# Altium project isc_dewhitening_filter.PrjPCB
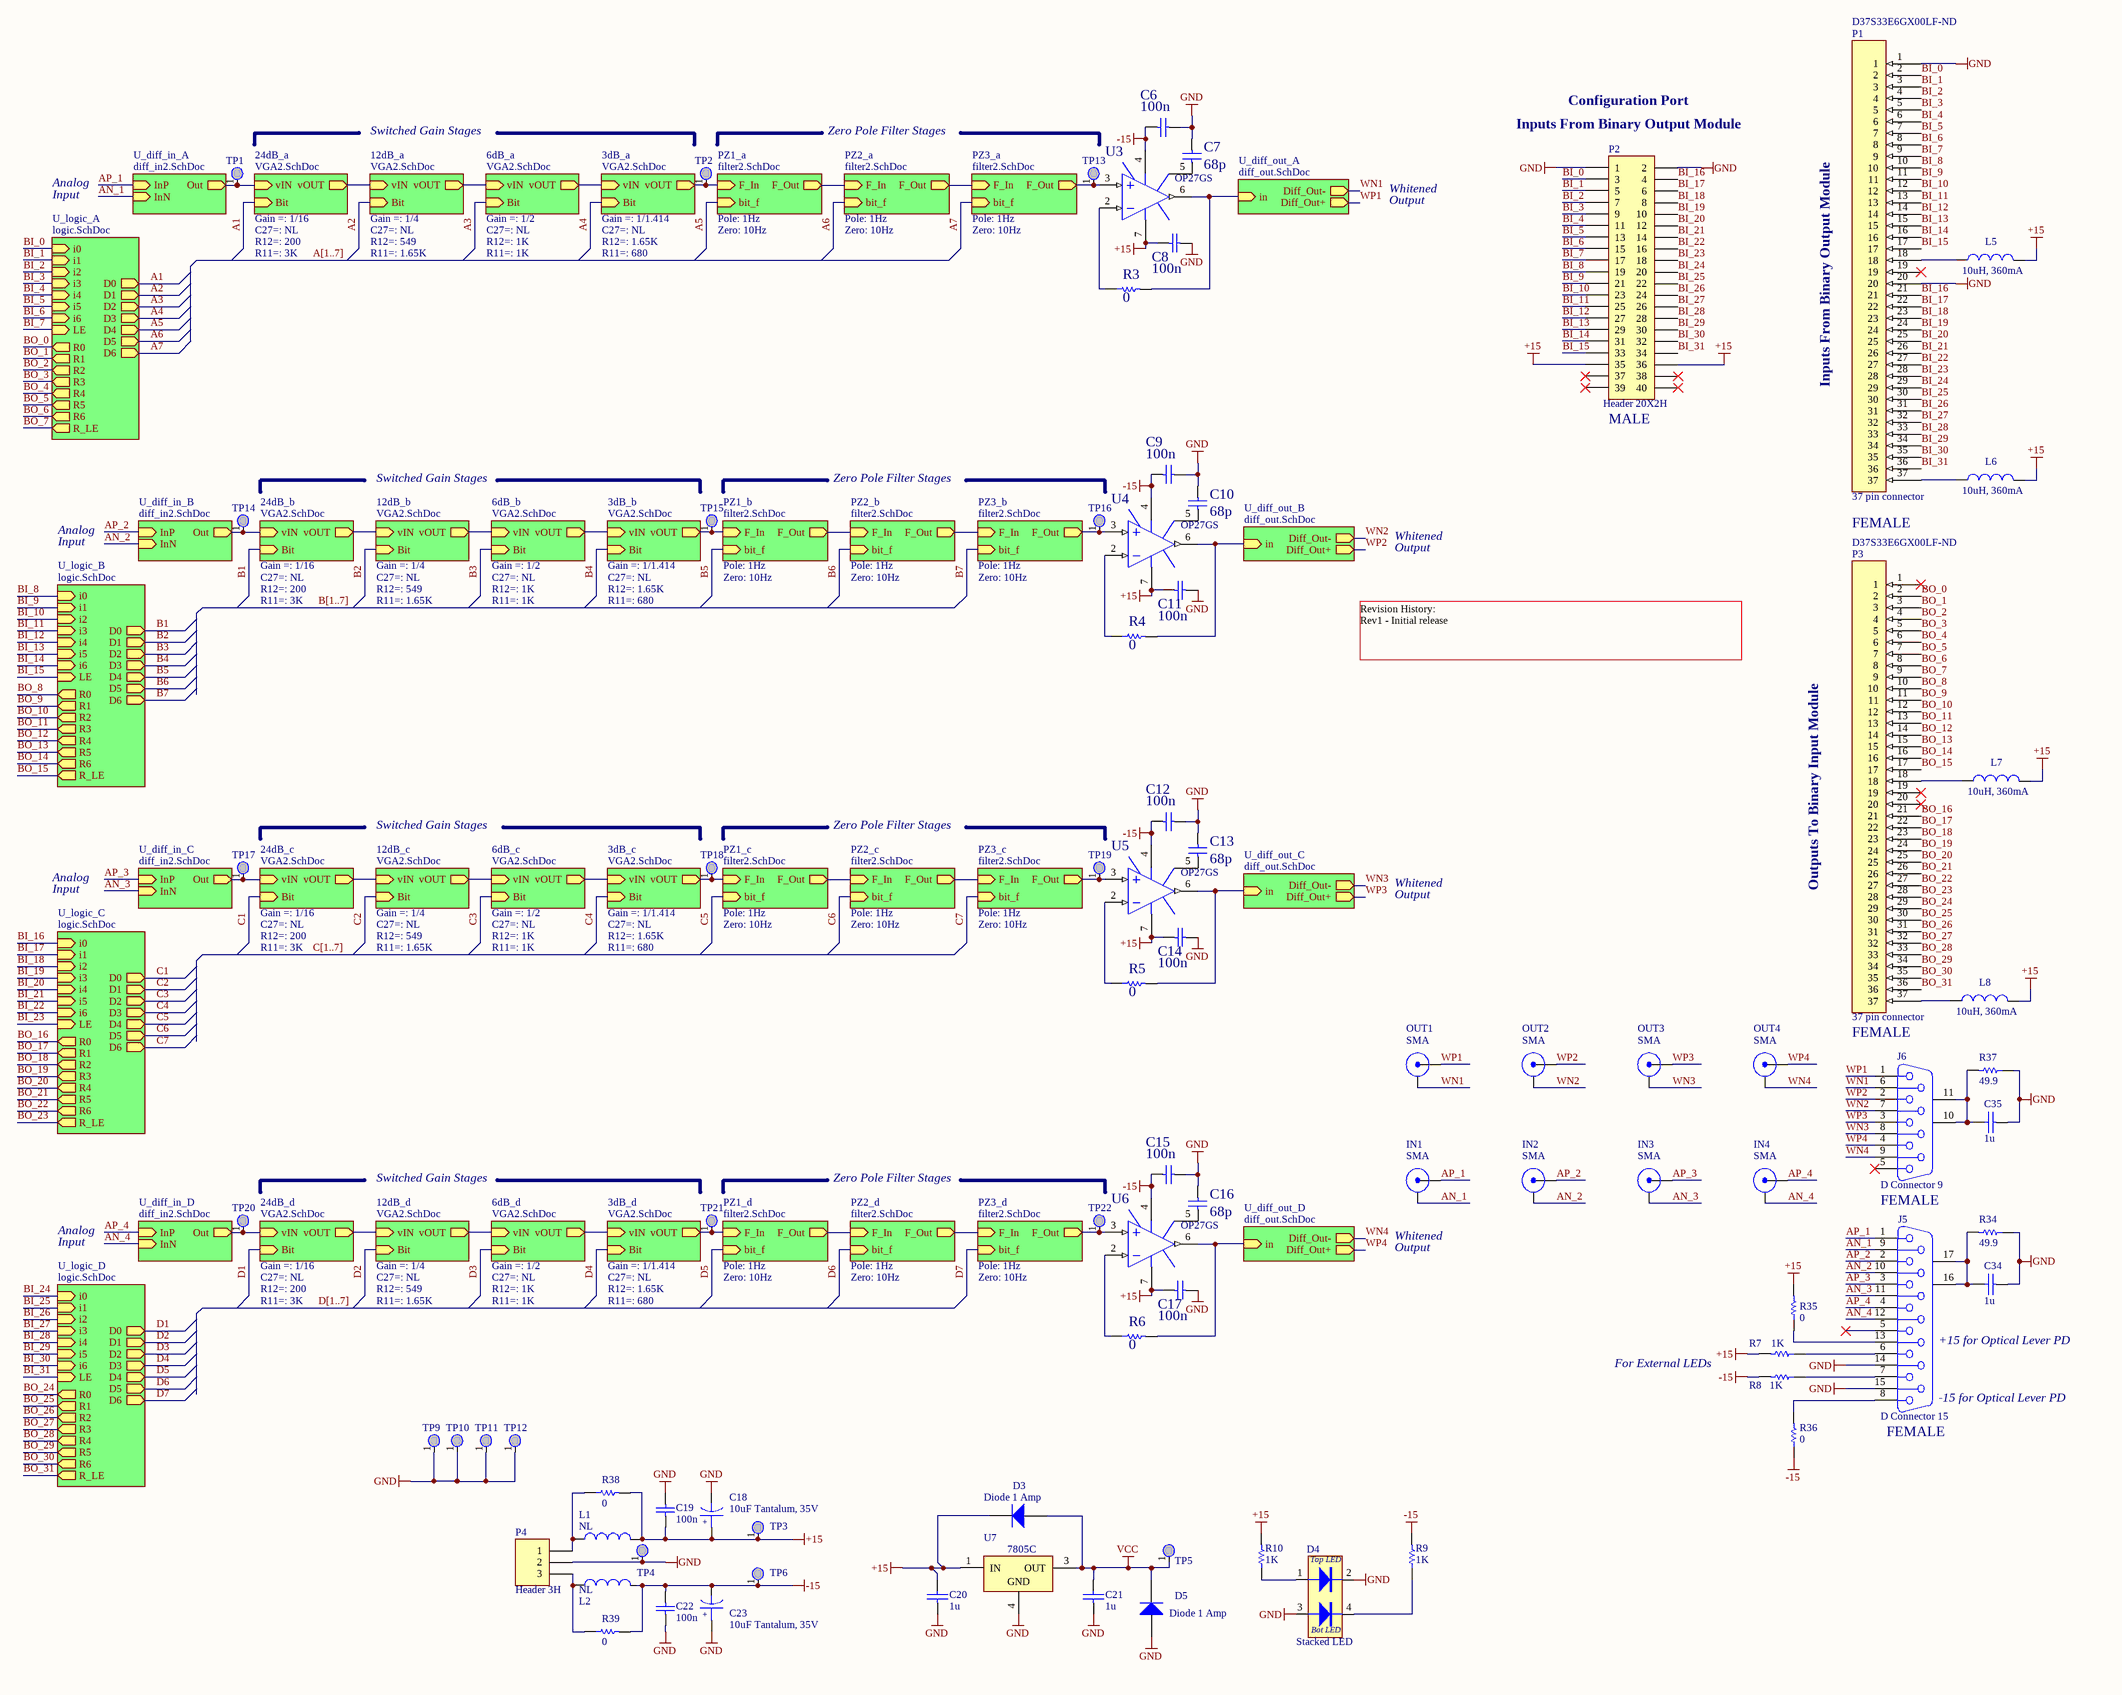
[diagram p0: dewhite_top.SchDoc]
DCC: D2500133; REV: 1
6 sheets, 550 parts. Net scope: hierarchical (ports join the sheet entries above them; power ports are global).
Board file: isc_dewhitening_filter.PcbDoc
Sheets:
  dewhite_top.SchDoc
    24dB_a = VGA2.SchDoc
    12dB_a = VGA2.SchDoc
    6dB_a = VGA2.SchDoc
    3dB_a = VGA2.SchDoc
    U_diff_in_A = diff_in2.SchDoc
    U_diff_out_A = diff_out.SchDoc
    U_logic_A = logic.SchDoc
    U_diff_in_B = diff_in2.SchDoc
    U_diff_out_B = diff_out.SchDoc
    U_logic_B = logic.SchDoc
    U_diff_in_C = diff_in2.SchDoc
    U_diff_out_C = diff_out.SchDoc
    U_logic_C = logic.SchDoc
    U_diff_in_D = diff_in2.SchDoc
    U_diff_out_D = diff_out.SchDoc
    U_logic_D = logic.SchDoc
    24dB_b = VGA2.SchDoc
    12dB_b = VGA2.SchDoc
    12dB_c = VGA2.SchDoc
    12dB_d = VGA2.SchDoc
    24dB_c = VGA2.SchDoc
    24dB_d = VGA2.SchDoc
    6dB_b = VGA2.SchDoc
    6dB_c = VGA2.SchDoc
    6dB_d = VGA2.SchDoc
    3dB_b = VGA2.SchDoc
    3dB_c = VGA2.SchDoc
    3dB_d = VGA2.SchDoc
    PZ1_b = filter2.SchDoc
    PZ2_b = filter2.SchDoc
    PZ3_b = filter2.SchDoc
    PZ1_a = filter2.SchDoc
    PZ2_a = filter2.SchDoc
    PZ3_a = filter2.SchDoc
    PZ1_c = filter2.SchDoc
    PZ2_c = filter2.SchDoc
    PZ3_c = filter2.SchDoc
    PZ1_d = filter2.SchDoc
    PZ2_d = filter2.SchDoc
    PZ3_d = filter2.SchDoc

## Sheet dewhite_top.SchDoc: aLIGO ISC Dewhitening Filter
size C; SchematicNumber: DYYYYYYY-VX; PcbNumber: DXXXXXXX-VX; LastEdit: 06 Oct 2010; PageSetup: Record=PageOptions¦CenterHorizontal=True¦CenterVertical=True¦PrintScale=0.70¦XCorrection=1.00¦YCorrection=1.00¦PrintKind=0¦BorderSize=5000000¦LeftOffset=0¦BottomOffset=0¦Orientation=2¦PaperLength=4318¦PaperWidth=2794¦Scale=100¦PaperSource=7¦PrintQuality=600¦MediaType=1¦DitherType=10¦PaperKind=11x17¦PrintScaleMode=1; Organization: LIGO Laboratory; Address1: California Institute of Technology; Address2: Massachusetts Institute of Technology; DocumentNumber: D2500133; Revision: 1; SheetNumber: 1; SheetTotal: 6; Engineer: R. Abbott/D. Sigg

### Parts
C6  100n  [3216[1206]]
C7  68p  [3216[1206]]
C8  100n  [3216[1206]]
C9  100n  [3216[1206]]
C10  68p  [3216[1206]]
C11  100n  [3216[1206]]
C12  100n  [3216[1206]]
C13  68p  [3216[1206]]
C14  100n  [3216[1206]]
C15  100n  [3216[1206]]
C16  68p  [3216[1206]]
C17  100n  [3216[1206]]
C18  10uF Tantalum, 35V  [7343-31]
C19  100n  [3216[1206]]
C20  1u  [3216[1206]]
C21  1u  [3216[1206]]
C22  100n  [3216[1206]]
C23  10uF Tantalum, 35V  [7343-31]
C34  1u  [3216[1206]]
C35  1u  [3216[1206]]
D3  value Diode 1 Amp  [sod123]  (hidden comment: 60V, 1A Schottky)
D4  Stacked LED  [my LUMEX Dual LED]
D5  value Diode 1 Amp  [sod123]  (hidden comment: 60V, 1A Schottky)
IN1  SMA  [SMA]
IN2  SMA  [SMA]
IN3  SMA  [SMA]
IN4  SMA  [SMA]
J5  D Connector 15  [DSUB1.385-2H15]
J6  D Connector 9  [DSUB1.385-2H9]
L1  NL  [1812]
L2  NL  [1812]
L5  10uH, 360mA  [1812]
L6  10uH, 360mA  [1812]
L7  10uH, 360mA  [1812]
L8  10uH, 360mA  [1812]
OUT1  SMA  [SMA]
OUT2  SMA  [SMA]
OUT3  SMA  [SMA]
OUT4  SMA  [SMA]
P1  37 pin connector  Supplier Part Number 1: D37S33E6GX00LF-ND  [DB37/F/RA/125MT]
P2  Header 20X2H  [MY_40-pin_Header_RA]
P3  37 pin connector  Supplier Part Number 1: D37S33E6GX00LF-ND  [DB37/F/RA/125MT]
P4  Header 3H  [Molex_156_RA_3]
R3  0  [3216[1206]]
R4  0  [3216[1206]]
R5  0  [3216[1206]]
R6  0  [3216[1206]]
R7  1K  [3216[1206]]
R8  1K  [3216[1206]]
R9  1K  [3216[1206]]
R10  1K  [3216[1206]]
R34  49.9  [3216[1206]]
R35  0  [3216[1206]]
R36  0  [3216[1206]]
R37  49.9  [3216[1206]]
R38  0  [3216[1206]]
R39  0  [3216[1206]]
TP1  TEST POINT  [TP_SMT_MICRO]  (value not drawn)
TP2  TEST POINT  [TP_SMT_MICRO]  (value not drawn)
TP3  TEST POINT  [TP_SMT_MICRO]  (value not drawn)
TP4  TEST POINT  [TP_SMT_MICRO]  (value not drawn)
TP5  TEST POINT  [TP_SMT_MICRO]  (value not drawn)
TP6  TEST POINT  [TP_SMT_MICRO]  (value not drawn)
TP9  TEST POINT  [TP_SMT_MICRO]  (value not drawn)
TP10  TEST POINT  [TP_SMT_MICRO]  (value not drawn)
TP11  TEST POINT  [TP_SMT_MICRO]  (value not drawn)
TP12  TEST POINT  [TP_SMT_MICRO]  (value not drawn)
TP13  TEST POINT  [TP_SMT_MICRO]  (value not drawn)
TP14  TEST POINT  [TP_SMT_MICRO]  (value not drawn)
TP15  TEST POINT  [TP_SMT_MICRO]  (value not drawn)
TP16  TEST POINT  [TP_SMT_MICRO]  (value not drawn)
TP17  TEST POINT  [TP_SMT_MICRO]  (value not drawn)
TP18  TEST POINT  [TP_SMT_MICRO]  (value not drawn)
TP19  TEST POINT  [TP_SMT_MICRO]  (value not drawn)
TP20  TEST POINT  [TP_SMT_MICRO]  (value not drawn)
TP21  TEST POINT  [TP_SMT_MICRO]  (value not drawn)
TP22  TEST POINT  [TP_SMT_MICRO]  (value not drawn)
U3  OP27GS  [SOIC127P600-8N]
U4  OP27GS  [SOIC127P600-8N]
U5  OP27GS  [SOIC127P600-8N]
U6  OP27GS  [SOIC127P600-8N]
U7  7805C  [MY_TO220]

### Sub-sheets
3dB_a = VGA2.SchDoc: Bit (in), vIN (in), vOUT (out)  | R12_value: 1.65K; R11_value: 680; C27_value: NL; Gain =: 1/1.414; C27=: NL; R12=: 1.65K; R11=: 680
3dB_b = VGA2.SchDoc: Bit (in), vIN (in), vOUT (out)  | R12_value: 1.65K; R11_value: 680; C27_value: NL; Gain =: 1/1.414; C27=: NL; R12=: 1.65K; R11=: 680
3dB_c = VGA2.SchDoc: Bit (in), vIN (in), vOUT (out)  | R12_value: 1.65K; R11_value: 680; C27_value: NL; Gain =: 1/1.414; C27=: NL; R12=: 1.65K; R11=: 680
3dB_d = VGA2.SchDoc: Bit (in), vIN (in), vOUT (out)  | R12_value: 1.65K; R11_value: 680; C27_value: NL; Gain =: 1/1.414; C27=: NL; R12=: 1.65K; R11=: 680
6dB_a = VGA2.SchDoc: Bit (in), vIN (in), vOUT (out)  | C27_value: NL; Gain =: 1/2; R12_Value: 1K; R11_value: 1K; R12=: 1K; R11=: 1K; C27=: NL
6dB_b = VGA2.SchDoc: Bit (in), vIN (in), vOUT (out)  | C27_value: NL; Gain =: 1/2; R12_Value: 1K; R11_value: 1K; R12=: 1K; R11=: 1K; C27=: NL
6dB_c = VGA2.SchDoc: Bit (in), vIN (in), vOUT (out)  | C27_value: NL; Gain =: 1/2; R12_Value: 1K; R11_value: 1K; R12=: 1K; R11=: 1K; C27=: NL
6dB_d = VGA2.SchDoc: Bit (in), vIN (in), vOUT (out)  | C27_value: NL; Gain =: 1/2; R12_Value: 1K; R11_value: 1K; R12=: 1K; R11=: 1K; C27=: NL
12dB_a = VGA2.SchDoc: Bit (in), vIN (in), vOUT (out)  | C27_value: NL; Gain =: 1/4; R12=: 549; R12_value: 549; R11=: 1.65K; R11_value: 1.65K; C27=: NL
12dB_b = VGA2.SchDoc: Bit (in), vIN (in), vOUT (out)  | C27_value: NL; Gain =: 1/4; R12=: 549; R12_value: 549; R11=: 1.65K; R11_value: 1.65K; C27=: NL
12dB_c = VGA2.SchDoc: Bit (in), vIN (in), vOUT (out)  | C27_value: NL; Gain =: 1/4; R12=: 549; R12_value: 549; R11=: 1.65K; R11_value: 1.65K; C27=: NL
12dB_d = VGA2.SchDoc: Bit (in), vIN (in), vOUT (out)  | C27_value: NL; Gain =: 1/4; R12=: 549; R12_value: 549; R11=: 1.65K; R11_value: 1.65K; C27=: NL
24dB_a = VGA2.SchDoc: Bit (in), vIN (in), vOUT (out)  | C27=: NL; C27_value: NL; R12=: 200; R11=: 3K; R11_value: 3K; R12_value: 200; Gain =: 1/16
24dB_b = VGA2.SchDoc: Bit (in), vIN (in), vOUT (out)  | C27=: NL; C27_value: NL; R12=: 200; R11=: 3K; R11_value: 3K; R12_value: 200; Gain =: 1/16
24dB_c = VGA2.SchDoc: Bit (in), vIN (in), vOUT (out)  | C27=: NL; C27_value: NL; R12=: 200; R11=: 3K; R11_value: 3K; R12_value: 200; Gain =: 1/16
24dB_d = VGA2.SchDoc: Bit (in), vIN (in), vOUT (out)  | C27=: NL; C27_value: NL; R12=: 200; R11=: 3K; R11_value: 3K; R12_value: 200; Gain =: 1/16
PZ1_a = filter2.SchDoc: bit_f (in), F_Out (out), F_In (in)  | Pole: 1Hz; Zero: 10Hz; C5_value: 10e-6
PZ1_b = filter2.SchDoc: bit_f (in), F_Out (out), F_In (in)  | Pole: 1Hz; Zero: 10Hz; C5_value: 10e-6
PZ1_c = filter2.SchDoc: bit_f (in), F_Out (out), F_In (in)  | Pole: 1Hz; Zero: 10Hz; C5_value: 10e-6
PZ1_d = filter2.SchDoc: bit_f (in), F_Out (out), F_In (in)  | Pole: 1Hz; Zero: 10Hz; C5_value: 10e-6
PZ2_a = filter2.SchDoc: bit_f (in), F_Out (out), F_In (in)  | Pole: 1Hz; Zero: 10Hz; C5_value: 10e-6
PZ2_b = filter2.SchDoc: bit_f (in), F_Out (out), F_In (in)  | Pole: 1Hz; Zero: 10Hz; C5_value: 10e-6
PZ2_c = filter2.SchDoc: bit_f (in), F_Out (out), F_In (in)  | Pole: 1Hz; Zero: 10Hz; C5_value: 10e-6
PZ2_d = filter2.SchDoc: bit_f (in), F_Out (out), F_In (in)  | Pole: 1Hz; Zero: 10Hz; C5_value: 10e-6
PZ3_a = filter2.SchDoc: bit_f (in), F_Out (out), F_In (in)  | Pole: 1Hz; Zero: 10Hz; C5_value: 10e-6
PZ3_b = filter2.SchDoc: bit_f (in), F_Out (out), F_In (in)  | Pole: 1Hz; Zero: 10Hz; C5_value: 10e-6
PZ3_c = filter2.SchDoc: bit_f (in), F_Out (out), F_In (in)  | Pole: 1Hz; Zero: 10Hz; C5_value: 10e-6
PZ3_d = filter2.SchDoc: bit_f (in), F_Out (out), F_In (in)  | Pole: 1Hz; Zero: 10Hz; C5_value: 10e-6
U_diff_in_A = diff_in2.SchDoc: InP (in), InN (in), Out (out)
U_diff_in_B = diff_in2.SchDoc: InP (in), InN (in), Out (out)
U_diff_in_C = diff_in2.SchDoc: InP (in), InN (in), Out (out)
U_diff_in_D = diff_in2.SchDoc: InP (in), InN (in), Out (out)
U_diff_out_A = diff_out.SchDoc: Diff_Out- (out), Diff_Out+ (out), in (in)
U_diff_out_B = diff_out.SchDoc: Diff_Out- (out), Diff_Out+ (out), in (in)
U_diff_out_C = diff_out.SchDoc: Diff_Out- (out), Diff_Out+ (out), in (in)
U_diff_out_D = diff_out.SchDoc: Diff_Out- (out), Diff_Out+ (out), in (in)
U_logic_A = logic.SchDoc: D0 (out), D1 (out), D2 (out), D3 (out), D4 (out), D5 (out), D6 (out), R0 (out), R1 (out), R2 (out), R3 (out), R4 (out), R5 (out), R6 (out), R_LE (out), i0 (in), i1 (in), i2 (in), i3 (in), i4 (in), i5 (in), i6 (in), LE (in)
U_logic_B = logic.SchDoc: D0 (out), D1 (out), D2 (out), D3 (out), D4 (out), D5 (out), D6 (out), R0 (out), R1 (out), R2 (out), R3 (out), R4 (out), R5 (out), R6 (out), R_LE (out), i0 (in), i1 (in), i2 (in), i3 (in), i4 (in), i5 (in), i6 (in), LE (in)
U_logic_C = logic.SchDoc: D0 (out), D1 (out), D2 (out), D3 (out), D4 (out), D5 (out), D6 (out), R0 (out), R1 (out), R2 (out), R3 (out), R4 (out), R5 (out), R6 (out), R_LE (out), i0 (in), i1 (in), i2 (in), i3 (in), i4 (in), i5 (in), i6 (in), LE (in)
U_logic_D = logic.SchDoc: D0 (out), D1 (out), D2 (out), D3 (out), D4 (out), D5 (out), D6 (out), R0 (out), R1 (out), R2 (out), R3 (out), R4 (out), R5 (out), R6 (out), R_LE (out), i0 (in), i1 (in), i2 (in), i3 (in), i4 (in), i5 (in), i6 (in), LE (in)

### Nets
+15: C8.2 C11.2 C14.2 C17.2 C18.1 C19.1 C20.2 D3.2(K) L1.2 L5.2 L6.2 L7.2 L8.2 P2.35 P2.36 R7.2 R10.2 R35.2 R38.2 TP3.1 U3.7(V+) U4.7(V+) U5.7(V+) U6.7(V+) U7.1(IN)
-15: C6.2 C9.2 C12.2 C15.2 C22.1 C23.2 L2.2 R8.2 R9.2 R36.1 R39.2 TP6.1 U3.4(V-) U4.4(V-) U5.4(V-) U6.4(V-)
GND: C6.1 C7.1 C8.1 C9.1 C10.1 C11.1 C12.1 C13.1 C14.1 C15.1 C16.1 C17.1 C18.2 C19.2 C20.1 C21.1 C22.2 C23.1 C34.1 C35.1 D4.2(CATHODE) D4.3(ANODE) D5.1(A) J5.14 J5.15 P1.1 P1.20 P2.1 P2.2 P4.2 R34.1 R37.1 TP4.1 TP9.1 TP10.1 TP11.1 TP12.1 U7.4(GND)
VCC: C21.2 D3.1(A) D5.2(K) TP5.1 U7.3(OUT)
A1: sheet 24dB_a/Bit, sheet U_logic_A/D0
A2: sheet 12dB_a/Bit, sheet U_logic_A/D1
A3: sheet 6dB_a/Bit, sheet U_logic_A/D2
A4: sheet 3dB_a/Bit, sheet U_logic_A/D3
A5: sheet U_logic_A/D4, sheet PZ1_a/bit_f
A6: sheet U_logic_A/D5, sheet PZ2_a/bit_f
A7: sheet U_logic_A/D6, sheet PZ3_a/bit_f
AN_1: IN1.2(Y) J5.9 ; sheet U_diff_in_A/InN
AN_2: IN2.2(Y) J5.10 ; sheet U_diff_in_B/InN
AN_3: IN3.2(Y) J5.11 ; sheet U_diff_in_C/InN
AN_4: IN4.2(Y) J5.12 ; sheet U_diff_in_D/InN
AP_1: IN1.1(X) J5.1 ; sheet U_diff_in_A/InP
AP_2: IN2.1(X) J5.2 ; sheet U_diff_in_B/InP
AP_3: IN3.1(X) J5.3 ; sheet U_diff_in_C/InP
AP_4: IN4.1(X) J5.4 ; sheet U_diff_in_D/InP
B1: sheet U_logic_B/D0, sheet 24dB_b/Bit
B2: sheet U_logic_B/D1, sheet 12dB_b/Bit
B3: sheet U_logic_B/D2, sheet 6dB_b/Bit
B4: sheet U_logic_B/D3, sheet 3dB_b/Bit
B5: sheet U_logic_B/D4, sheet PZ1_b/bit_f
B6: sheet U_logic_B/D5, sheet PZ2_b/bit_f
B7: sheet U_logic_B/D6, sheet PZ3_b/bit_f
BI_0: P1.2 P2.3 ; sheet U_logic_A/i0
BI_1: P1.3 P2.5 ; sheet U_logic_A/i1
BI_2: P1.4 P2.7 ; sheet U_logic_A/i2
BI_3: P1.5 P2.9 ; sheet U_logic_A/i3
BI_4: P1.6 P2.11 ; sheet U_logic_A/i4
BI_5: P1.7 P2.13 ; sheet U_logic_A/i5
BI_6: P1.8 P2.15 ; sheet U_logic_A/i6
BI_7: P1.9 P2.17 ; sheet U_logic_A/LE
BI_8: P1.10 P2.19 ; sheet U_logic_B/i0
BI_9: P1.11 P2.21 ; sheet U_logic_B/i1
BI_10: P1.12 P2.23 ; sheet U_logic_B/i2
BI_11: P1.13 P2.25 ; sheet U_logic_B/i3
BI_12: P1.14 P2.27 ; sheet U_logic_B/i4
BI_13: P1.15 P2.29 ; sheet U_logic_B/i5
BI_14: P1.16 P2.31 ; sheet U_logic_B/i6
BI_15: P1.17 P2.33 ; sheet U_logic_B/LE
BI_16: P1.21 P2.4 ; sheet U_logic_C/i0
BI_17: P1.22 P2.6 ; sheet U_logic_C/i1
BI_18: P1.23 P2.8 ; sheet U_logic_C/i2
BI_19: P1.24 P2.10 ; sheet U_logic_C/i3
BI_20: P1.25 P2.12 ; sheet U_logic_C/i4
BI_21: P1.26 P2.14 ; sheet U_logic_C/i5
BI_22: P1.27 P2.16 ; sheet U_logic_C/i6
BI_23: P1.28 P2.18 ; sheet U_logic_C/LE
BI_24: P1.29 P2.20 ; sheet U_logic_D/i0
BI_25: P1.30 P2.22 ; sheet U_logic_D/i1
BI_26: P1.31 P2.24 ; sheet U_logic_D/i2
BI_27: P1.32 P2.26 ; sheet U_logic_D/i3
BI_28: P1.33 P2.28 ; sheet U_logic_D/i4
BI_29: P1.34 P2.30 ; sheet U_logic_D/i5
BI_30: P1.35 P2.32 ; sheet U_logic_D/i6
BI_31: P1.36 P2.34 ; sheet U_logic_D/LE
BO_0: P3.2 ; sheet U_logic_A/R0
BO_1: P3.3 ; sheet U_logic_A/R1
BO_2: P3.4 ; sheet U_logic_A/R2
BO_3: P3.5 ; sheet U_logic_A/R3
BO_4: P3.6 ; sheet U_logic_A/R4
BO_5: P3.7 ; sheet U_logic_A/R5
BO_6: P3.8 ; sheet U_logic_A/R6
BO_7: P3.9 ; sheet U_logic_A/R_LE
BO_8: P3.10 ; sheet U_logic_B/R0
BO_9: P3.11 ; sheet U_logic_B/R1
BO_10: P3.12 ; sheet U_logic_B/R2
BO_11: P3.13 ; sheet U_logic_B/R3
BO_12: P3.14 ; sheet U_logic_B/R4
BO_13: P3.15 ; sheet U_logic_B/R5
BO_14: P3.16 ; sheet U_logic_B/R6
BO_15: P3.17 ; sheet U_logic_B/R_LE
BO_16: P3.21 ; sheet U_logic_C/R0
BO_17: P3.22 ; sheet U_logic_C/R1
BO_18: P3.23 ; sheet U_logic_C/R2
BO_19: P3.24 ; sheet U_logic_C/R3
BO_20: P3.25 ; sheet U_logic_C/R4
BO_21: P3.26 ; sheet U_logic_C/R5
BO_22: P3.27 ; sheet U_logic_C/R6
BO_23: P3.28 ; sheet U_logic_C/R_LE
BO_24: P3.29 ; sheet U_logic_D/R0
BO_25: P3.30 ; sheet U_logic_D/R1
BO_26: P3.31 ; sheet U_logic_D/R2
BO_27: P3.32 ; sheet U_logic_D/R3
BO_28: P3.33 ; sheet U_logic_D/R4
BO_29: P3.34 ; sheet U_logic_D/R5
BO_30: P3.35 ; sheet U_logic_D/R6
BO_31: P3.36 ; sheet U_logic_D/R_LE
C1: sheet U_logic_C/D0, sheet 24dB_c/Bit
C2: sheet U_logic_C/D1, sheet 12dB_c/Bit
C3: sheet U_logic_C/D2, sheet 6dB_c/Bit
C4: sheet U_logic_C/D3, sheet 3dB_c/Bit
C5: sheet U_logic_C/D4, sheet PZ1_c/bit_f
C6: sheet U_logic_C/D5, sheet PZ2_c/bit_f
C7: sheet U_logic_C/D6, sheet PZ3_c/bit_f
D1: sheet U_logic_D/D0, sheet 24dB_d/Bit
D2: sheet U_logic_D/D1, sheet 12dB_d/Bit
D3: sheet U_logic_D/D2, sheet 6dB_d/Bit
D4: sheet U_logic_D/D3, sheet 3dB_d/Bit
D5: sheet U_logic_D/D4, sheet PZ1_d/bit_f
D6: sheet U_logic_D/D5, sheet PZ2_d/bit_f
D7: sheet U_logic_D/D6, sheet PZ3_d/bit_f
WN1: J6.6 OUT1.2(Y) ; sheet U_diff_out_A/Diff_Out-
WN2: J6.7 OUT2.2(Y) ; sheet U_diff_out_B/Diff_Out-
WN3: J6.8 OUT3.2(Y) ; sheet U_diff_out_C/Diff_Out-
WN4: J6.9 OUT4.2(Y) ; sheet U_diff_out_D/Diff_Out-
WP1: J6.1 OUT1.1(X) ; sheet U_diff_out_A/Diff_Out+
WP2: J6.2 OUT2.1(X) ; sheet U_diff_out_B/Diff_Out+
WP3: J6.3 OUT3.1(X) ; sheet U_diff_out_C/Diff_Out+
WP4: J6.4 OUT4.1(X) ; sheet U_diff_out_D/Diff_Out+
NetC7_2: C7.2 U3.5(NUL)
NetC10_2: C10.2 U4.5(NUL)
NetC13_2: C13.2 U5.5(NUL)
NetC16_2: C16.2 U6.5(NUL)
NetC34_2: C34.2 J5.16(MH1) J5.17(MH2) R34.2
NetC35_2: C35.2 J6.10(MH1) J6.11(MH2) R37.2
NetC39_U_diff_in_A_2: TP1.1 ; sheet 24dB_a/vIN, sheet U_diff_in_A/Out
NetC39_U_diff_in_B_2: TP14.1 ; sheet U_diff_in_B/Out, sheet 24dB_b/vIN
NetC39_U_diff_in_C_2: TP17.1 ; sheet U_diff_in_C/Out, sheet 24dB_c/vIN
NetC39_U_diff_in_D_2: TP20.1 ; sheet U_diff_in_D/Out, sheet 24dB_d/vIN
NetD4_1: D4.1(COM) R10.1
NetD4_4: D4.4(ANODE) R9.1
NetJ5_6: J5.6 R7.1
NetJ5_7: J5.7 R8.1
NetJ5_8: J5.8 R36.2
NetJ5_13: J5.13 R35.1
NetL1_1: L1.1 P4.1 R38.1
NetL2_1: L2.1 P4.3 R39.1
NetL5_1: L5.1 P1.18
NetL6_1: L6.1 P1.37
NetL7_1: L7.1 P3.18
NetL8_1: L8.1 P3.37
NetR3_1: R3.1 U3.2(IN-)
NetR3_2: R3.2 U3.6(OUT) ; sheet U_diff_out_A/in
NetR4_1: R4.1 U4.2(IN-)
NetR4_2: R4.2 U4.6(OUT) ; sheet U_diff_out_B/in
NetR5_1: R5.1 U5.2(IN-)
NetR5_2: R5.2 U5.6(OUT) ; sheet U_diff_out_C/in
NetR6_1: R6.1 U6.2(IN-)
NetR6_2: R6.2 U6.6(OUT) ; sheet U_diff_out_D/in
NetTP2_1: TP2.1 ; sheet 3dB_a/vOUT, sheet PZ1_a/F_In
NetTP13_1: TP13.1 U3.3(IN+) ; sheet PZ3_a/F_Out
NetTP15_1: TP15.1 ; sheet 3dB_b/vOUT, sheet PZ1_b/F_In
NetTP16_1: TP16.1 U4.3(IN+) ; sheet PZ3_b/F_Out
NetTP18_1: TP18.1 ; sheet 3dB_c/vOUT, sheet PZ1_c/F_In
NetTP19_1: TP19.1 U5.3(IN+) ; sheet PZ3_c/F_Out
NetTP21_1: TP21.1 ; sheet 3dB_d/vOUT, sheet PZ1_d/F_In
NetTP22_1: TP22.1 U6.3(IN+) ; sheet PZ3_d/F_Out
NetU2_PZ1_a_11: sheet PZ1_a/F_Out, sheet PZ2_a/F_In
NetU2_PZ1_b_11: sheet PZ1_b/F_Out, sheet PZ2_b/F_In
NetU2_PZ1_c_11: sheet PZ1_c/F_Out, sheet PZ2_c/F_In
NetU2_PZ1_d_11: sheet PZ1_d/F_Out, sheet PZ2_d/F_In
NetU2_PZ2_a_11: sheet PZ2_a/F_Out, sheet PZ3_a/F_In
NetU2_PZ2_b_11: sheet PZ2_b/F_Out, sheet PZ3_b/F_In
NetU2_PZ2_c_11: sheet PZ2_c/F_Out, sheet PZ3_c/F_In
NetU2_PZ2_d_11: sheet PZ2_d/F_Out, sheet PZ3_d/F_In
NetU8_3dB_a_4: sheet 6dB_a/vOUT, sheet 3dB_a/vIN
NetU8_3dB_b_4: sheet 6dB_b/vOUT, sheet 3dB_b/vIN
NetU8_3dB_c_4: sheet 6dB_c/vOUT, sheet 3dB_c/vIN
NetU8_3dB_d_4: sheet 6dB_d/vOUT, sheet 3dB_d/vIN
NetU8_6dB_a_4: sheet 12dB_a/vOUT, sheet 6dB_a/vIN
NetU8_6dB_b_4: sheet 12dB_b/vOUT, sheet 6dB_b/vIN
NetU8_6dB_c_4: sheet 12dB_c/vOUT, sheet 6dB_c/vIN
NetU8_6dB_d_4: sheet 12dB_d/vOUT, sheet 6dB_d/vIN
NetU8_12dB_a_4: sheet 24dB_a/vOUT, sheet 12dB_a/vIN
NetU8_12dB_b_4: sheet 24dB_b/vOUT, sheet 12dB_b/vIN
NetU8_12dB_c_4: sheet 12dB_c/vIN, sheet 24dB_c/vOUT
NetU8_12dB_d_4: sheet 12dB_d/vIN, sheet 24dB_d/vOUT

Not connected (* = marked no-connect by the designer): J5 5*; J6 5*; P1 19*; P2 37* 38* 39* 40*; P3 1* 19* 20*; U3 1(NUL) 8(NC); U4 1(NUL) 8(NC); U5 1(NUL) 8(NC); U6 1(NUL) 8(NC)

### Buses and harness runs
bus A[1..7]
bus B[1..7]
bus C[1..7]
bus D[1..7]

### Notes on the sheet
- Configuration Port
- Switched Gain Stages
- Zero Pole Filter Stages
- (near P2) Inputs From Binary Output Module
- Analog
- Input
- Whitened
- Output
- Inputs From Binary Output Module
- (near P2) MALE
- FEMALE
- Revision History:
  Rev1 - Initial release
- Outputs To Binary Input Module
- (near IN1) Whitened
- For External LEDs
- (near J5) +15 for Optical Lever PD
- (near J5) -15 for Optical Lever PD
- (near J5) FEMALE

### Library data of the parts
C6-C17 C19 C22 = Cap: Capacitor
C18 C23 = CAPACITOR POL: Polarized Cap
C20 C21 C34 C35 = MYCAP: Capacitor
D3 D5 = Diode: Diode 1 Amp
D4 = Dual Stacked LED: Dual Green LED
IN1-IN4 OUT1-OUT4 = SMA: SMA, PCB Mount, Right Angle
J5 = D Connector 15: 15 Position, Right Angle, Receptacle Assembly; Value: 15 pin connector Receptacle
J6 = D Connector 9: 9 Position, Right Angle,Receptacle Assembly; Value: 9 pin connector Receptacle
L1 L2 L5-L8 = INDUCTOR
P1 P3 = 37 pin connector: Standard D-Subminiature Connector 37 pin; Value: 37 pin connector Receptacle
P2 = Header 20X2H: Header, 20-Pin, Dual row, Right Angle
P4 = Header 3H: Header, 3-Pin, Right Angle
R3-R10 R34-R39 = Res1: Resistor
TP1-TP6 TP9-TP22 = TESTPT: PCB Testpoint
U3-U6 = OP184ES: Video Operational Amplifier
U7 = MC7805CD2T: Three-Terminal Positive Voltage Regulator

## Sheet VGA2.SchDoc: Variable Gain Stage (Dewhitening)
size A; SchematicNumber: DYYYYYYY-VX; PcbNumber: DXXXXXXX-VX; LastEdit: 06 Oct 2010; Organization: LIGO Laboratory; Address1: California Institute of Technology; Address2: Massachusetts Institute of Technology; DocumentNumber: D2500133; Revision: 1; SheetNumber: 5; SheetTotal: 9; Engineer: R. Abbott/D. Sigg; PageSetup: Record=PageOptions¦CenterHorizontal=True¦CenterVertical=True¦PrintScale=1.40¦XCorrection=1.00¦YCorrection=1.00¦PrintKind=0¦BorderSize=5000000¦LeftOffset=0¦BottomOffset=0¦Orientation=2¦PaperLength=4318¦PaperWidth=2794¦Scale=100¦PaperSource=15¦PrintQuality=600¦MediaType=1¦DitherType=10¦PaperKind=11x17¦PrintScaleMode=1
Used 16 times, as channels 24dB_a, 12dB_a, 6dB_a, 3dB_a, 24dB_b, 12dB_b, 12dB_c, 12dB_d, 24dB_c, 24dB_d, 6dB_b, 6dB_c, 6dB_d, 3dB_b, 3dB_c, 3dB_d. Parts and nets are listed once, with the designators drawn on the sheet.
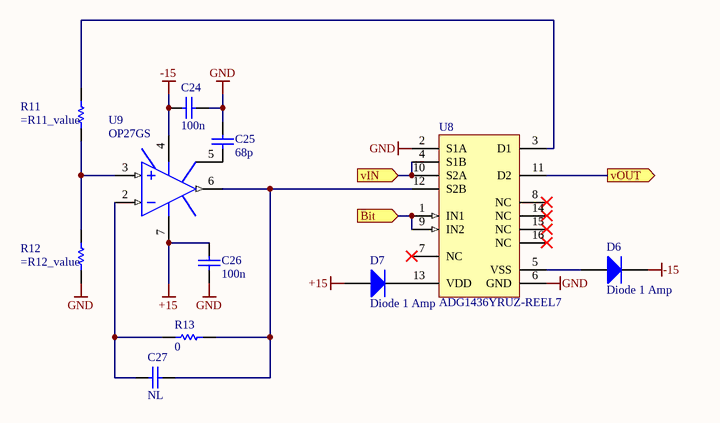
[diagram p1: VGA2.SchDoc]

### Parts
C24  100n  [3216[1206]]
C25  68p  [3216[1206]]
C26  100n  [3216[1206]]
C27  NL  [3216[1206]]
D6  value Diode 1 Amp  [sod123]  (hidden comment: 60V, 1A Schottky)
D7  value Diode 1 Amp  [sod123]  (hidden comment: 60V, 1A Schottky)
R11  (no value)  [3216[1206]]
R12  (no value)  [3216[1206]]
R13  0  [3216[1206]]
U8  ADG1436YRUZ-REEL7  [ADI-RU-16_L]
U9  OP27GS  [SOIC127P600-8N]

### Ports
Bit (in), vIN (in), vOUT (out)

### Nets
+15: C26.2 D7.1(A) U9.7(V+)
-15: C24.2 D6.2(K) U9.4(V-)
GND: C24.1 C25.1 C26.1 R12.1 U8.2(S1A) U8.6(GND)
Bit: U8.1(IN1) U8.9(IN2) ; port Bit
vIN: U8.4(S1B) U8.10(S2A) ; port vIN
vOUT: U8.11(D2) ; port vOUT
NetC25_2: C25.2 U9.5(NUL)
NetC27_1: C27.1 R13.2 U8.12(S2B) U9.6(OUT)
NetC27_2: C27.2 R13.1 U9.2(IN-)
NetD6_1: D6.1(A) U8.5(VSS)
NetD7_2: D7.2(K) U8.13(VDD)
NetR11_1: R11.1 R12.2 U9.3(IN+)
NetR11_2: R11.2 U8.3(D1)

Not connected (* = marked no-connect by the designer): U8 7(NC)* 8(NC)* 14(NC)* 15(NC)* 16(NC)*; U9 1(NUL) 8(NC)

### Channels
24dB_a: designators end in _24dB_a; ports Bit=A1 vIN=NetC39_U_diff_in_A_2 vOUT=NetU8_12dB_a_4
12dB_a: designators end in _12dB_a; ports Bit=A2 vIN=NetU8_12dB_a_4 vOUT=NetU8_6dB_a_4
6dB_a: designators end in _6dB_a; ports Bit=A3 vIN=NetU8_6dB_a_4 vOUT=NetU8_3dB_a_4
3dB_a: designators end in _3dB_a; ports Bit=A4 vIN=NetU8_3dB_a_4 vOUT=NetTP2_1
24dB_b: designators end in _24dB_b; ports Bit=B1 vIN=NetC39_U_diff_in_B_2 vOUT=NetU8_12dB_b_4
12dB_b: designators end in _12dB_b; ports Bit=B2 vIN=NetU8_12dB_b_4 vOUT=NetU8_6dB_b_4
12dB_c: designators end in _12dB_c; ports Bit=C2 vIN=NetU8_12dB_c_4 vOUT=NetU8_6dB_c_4
12dB_d: designators end in _12dB_d; ports Bit=D2 vIN=NetU8_12dB_d_4 vOUT=NetU8_6dB_d_4
24dB_c: designators end in _24dB_c; ports Bit=C1 vIN=NetC39_U_diff_in_C_2 vOUT=NetU8_12dB_c_4
24dB_d: designators end in _24dB_d; ports Bit=D1 vIN=NetC39_U_diff_in_D_2 vOUT=NetU8_12dB_d_4
6dB_b: designators end in _6dB_b; ports Bit=B3 vIN=NetU8_6dB_b_4 vOUT=NetU8_3dB_b_4
6dB_c: designators end in _6dB_c; ports Bit=C3 vIN=NetU8_6dB_c_4 vOUT=NetU8_3dB_c_4
6dB_d: designators end in _6dB_d; ports Bit=D3 vIN=NetU8_6dB_d_4 vOUT=NetU8_3dB_d_4
3dB_b: designators end in _3dB_b; ports Bit=B4 vIN=NetU8_3dB_b_4 vOUT=NetTP15_1
3dB_c: designators end in _3dB_c; ports Bit=C4 vIN=NetU8_3dB_c_4 vOUT=NetTP18_1
3dB_d: designators end in _3dB_d; ports Bit=D4 vIN=NetU8_3dB_d_4 vOUT=NetTP21_1

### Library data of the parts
C24-C27 = Cap: Capacitor
D6 D7 = Diode: Diode 1 Amp
R11-R13 = Res1: Resistor
U8 = CMP-0793-00126-1: +/-15 V / 12 V / +/-5 V, iCMOS, Dual SPDT Switch, 16-pin SOP (RU-16), Reel
U9 = OP184ES: Video Operational Amplifier

## Sheet diff_in2.SchDoc: Differential Receiver (Dewhitening)
size A; Organization: LIGO Laboratory; Address1: California Institute of Technology; Address2: Massachusetts Institute of Technology; DocumentNumber: D2500133; Revision: 1; SheetNumber: 3; SheetTotal: 9; Engineer: R. Abbott/D. Sigg; SchematicNumber: DYYYYYYY-VX; PcbNumber: DXXXXXXX-VX; LastEdit: 06 Oct 2010; PageSetup: Record=PageOptions¦CenterHorizontal=True¦CenterVertical=True¦PrintScale=1.07¦XCorrection=1.00¦YCorrection=1.00¦PrintKind=0¦BorderSize=5000000¦LeftOffset=0¦BottomOffset=0¦Orientation=2¦PaperLength=2794¦PaperWidth=2159¦Scale=100¦PaperSource=7¦PrintQuality=600¦MediaType=1¦DitherType=10¦PaperKind=Letter¦PrintScaleMode=1
Used 4 times, as channels U_diff_in_A, U_diff_in_B, U_diff_in_C, U_diff_in_D. Parts and nets are listed once, with the designators drawn on the sheet.
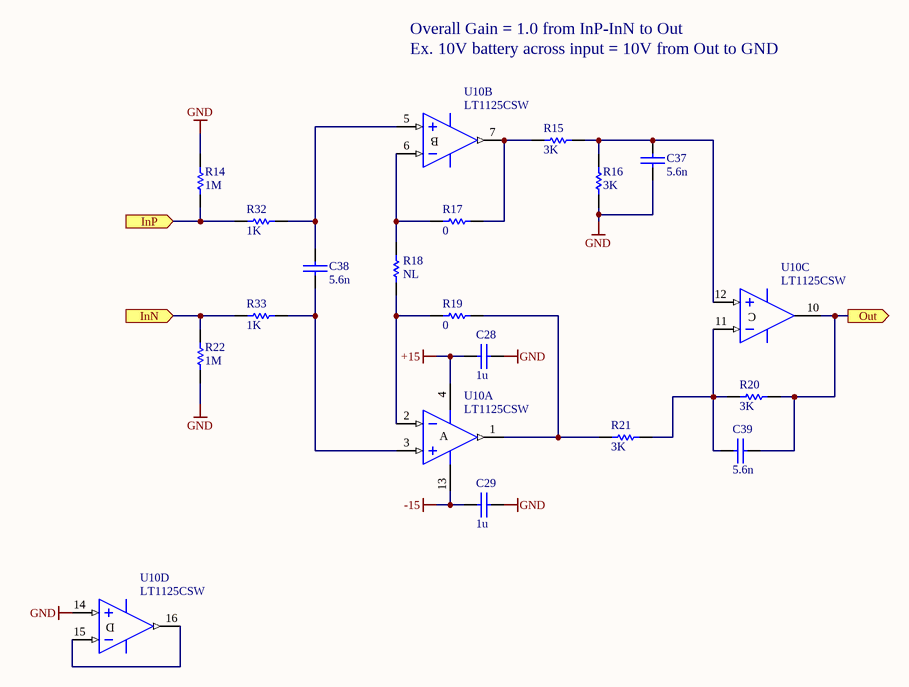
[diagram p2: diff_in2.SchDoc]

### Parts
C28  1u  [3216[1206]]
C29  1u  [3216[1206]]
C37  5.6n  [3216[1206]]
C38  5.6n  [3216[1206]]
C39  5.6n  [3216[1206]]
R14  1M  [3216[1206]]
R15  3K  [3216[1206]]
R16  3K  [3216[1206]]
R17  0  [3216[1206]]
R18  NL  [3216[1206]]
R19  0  [3216[1206]]
R20  3K  [3216[1206]]
R21  3K  [3216[1206]]
R22  1M  [3216[1206]]
R32  1K  [3216[1206]]
R33  1K  [3216[1206]]
U10  LT1125CSW  [SOIC127P1030-16N]  (parts A,B,C,D of 4)

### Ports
InN (in), InP (in), Out (out)

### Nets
+15: C28.1 U10.4(V+)
-15: C29.1 U10.13(V-)
GND: C28.2 C29.2 C37.1 R14.1 R16.2 R22.2 U10.14(IN+)
InN: R22.1 R33.2 ; port InN
InP: R14.2 R32.2 ; port InP
Out: C39.2 R20.1 U10.10(OUT) ; port Out
NetC37_2: C37.2 R15.1 R16.1 U10.12(IN+)
NetC38_1: C38.1 R33.1 U10.3(IN+)
NetC38_2: C38.2 R32.1 U10.5(IN+)
NetC39_1: C39.1 R20.2 R21.1 U10.11(IN-)
NetR15_2: R15.2 R17.1 U10.7(OUT)
NetR17_2: R17.2 R18.2 U10.6(IN-)
NetR18_1: R18.1 R19.2 U10.2(IN-)
NetR19_1: R19.1 R21.2 U10.1(OUT)
NetU10_15: U10.15(IN-) U10.16(OUT)

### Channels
U_diff_in_A: designators end in _U_diff_in_A; ports InN=AN_1 InP=AP_1 Out=NetC39_U_diff_in_A_2
U_diff_in_B: designators end in _U_diff_in_B; ports InN=AN_2 InP=AP_2 Out=NetC39_U_diff_in_B_2
U_diff_in_C: designators end in _U_diff_in_C; ports InN=AN_3 InP=AP_3 Out=NetC39_U_diff_in_C_2
U_diff_in_D: designators end in _U_diff_in_D; ports InN=AN_4 InP=AP_4 Out=NetC39_U_diff_in_D_2

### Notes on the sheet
- Overall Gain = 1.0 from InP-InN to Out
- Ex. 10V battery across input = 10V from Out to GND

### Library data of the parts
C28 C29 C37-C39 = MYCAP: Capacitor
R14-R22 R32 R33 = Res1: Resistor
U10 = LT1125CS: Quad Low Noise, High-Speed Precision Operational Amplifier

## Sheet diff_out.SchDoc: Differential Driver
size A; Organization: LIGO Laboratory; Address1: California Institute of Technology; Address2: Massachusetts Institute of Technology; DocumentNumber: D2500133; Revision: 1; SheetNumber: 9; SheetTotal: 9; Engineer: R.  Abbott; SchematicNumber: DYYYYYYY-VX; PcbNumber: DXXXXXXX-VX; LastEdit: 06 Oct 2010; PageSetup: Record=PageOptions¦CenterHorizontal=True¦CenterVertical=True¦PrintScale=1.07¦XCorrection=1.00¦YCorrection=1.00¦PrintKind=0¦BorderSize=5000000¦LeftOffset=0¦BottomOffset=0¦Orientation=2¦PaperLength=2794¦PaperWidth=2159¦Scale=100¦PaperSource=7¦PrintQuality=600¦MediaType=1¦DitherType=10¦PaperKind=Letter¦PrintScaleMode=1
Used 4 times, as channels U_diff_out_A, U_diff_out_B, U_diff_out_C, U_diff_out_D. Parts and nets are listed once, with the designators drawn on the sheet.
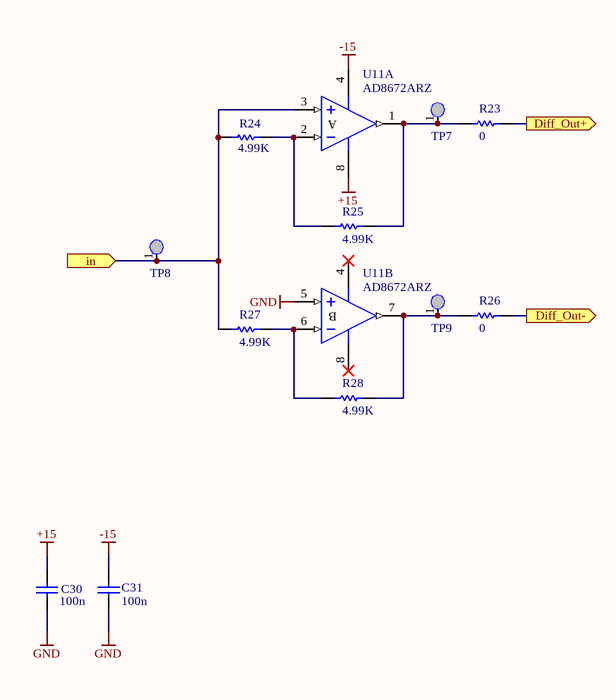
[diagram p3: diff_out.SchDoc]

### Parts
C30  100n  [3216[1206]]
C31  100n  [3216[1206]]
R23  0  [3216[1206]]
R24  4.99K  [3216[1206]]
R25  4.99K  [3216[1206]]
R26  0  [3216[1206]]
R27  4.99K  [3216[1206]]
R28  4.99K  [3216[1206]]
TP7  TEST POINT  [TP_SMT_MICRO]  (value not drawn)
TP8  TEST POINT  [TP_SMT_MICRO]  (value not drawn)
TP9  TEST POINT  [TP_SMT_MICRO]  (value not drawn)
U11  AD8672ARZ  [SOIC127P600-8N]  (parts A,B of 2)

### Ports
Diff_Out+ (out), Diff_Out- (out), in (in)

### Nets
+15: C30.1 U11.8(V+)
-15: C31.1 U11.4(V-)
GND: C30.2 C31.2 U11.5(IN+)
Diff_Out+: R23.2 ; port Diff_Out+
Diff_Out-: R26.2 ; port Diff_Out-
in: R24.1 R27.1 TP8.1 U11.3(IN+) ; port in
NetR23_1: R23.1 R25.2 TP7.1 U11.1(OUT)
NetR24_2: R24.2 R25.1 U11.2(IN-)
NetR26_1: R26.1 R28.2 TP9.1 U11.7(OUT)
NetR27_2: R27.2 R28.1 U11.6(IN-)

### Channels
U_diff_out_A: designators end in _U_diff_out_A; ports Diff_Out+=WP1 Diff_Out-=WN1 in=NetR3_2
U_diff_out_B: designators end in _U_diff_out_B; ports Diff_Out+=WP2 Diff_Out-=WN2 in=NetR4_2
U_diff_out_C: designators end in _U_diff_out_C; ports Diff_Out+=WP3 Diff_Out-=WN3 in=NetR5_2
U_diff_out_D: designators end in _U_diff_out_D; ports Diff_Out+=WP4 Diff_Out-=WN4 in=NetR6_2

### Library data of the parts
C30 C31 = Cap: Capacitor
R23-R28 = Res1: Resistor
TP7-TP9 = TESTPT: PCB Testpoint
U11 = AD826AR: High-Speed, Low-Power Dual Operational Amplifier

## Sheet logic.SchDoc: Switch Logic Circuit
size A; Organization: LIGO Laboratory; Address1: California Institute of Technology; Address2: Massachusetts Institute of Technology; DocumentNumber: D2500133; Revision: 1; SheetNumber: 8; SheetTotal: 9; Engineer: R.  Abbott; SchematicNumber: DYYYYYYY-VX; PcbNumber: DXXXXXXX-VX; LastEdit: 06 Oct 2010; PageSetup: Record=PageOptions¦CenterHorizontal=True¦CenterVertical=True¦PrintScale=1.07¦XCorrection=1.00¦YCorrection=1.00¦PrintKind=0¦BorderSize=5000000¦LeftOffset=0¦BottomOffset=0¦Orientation=2¦PaperLength=2794¦PaperWidth=2159¦Scale=100¦PaperSource=7¦PrintQuality=600¦MediaType=1¦DitherType=10¦PaperKind=Letter¦PrintScaleMode=1
Used 4 times, as channels U_logic_A, U_logic_B, U_logic_C, U_logic_D. Parts and nets are listed once, with the designators drawn on the sheet.
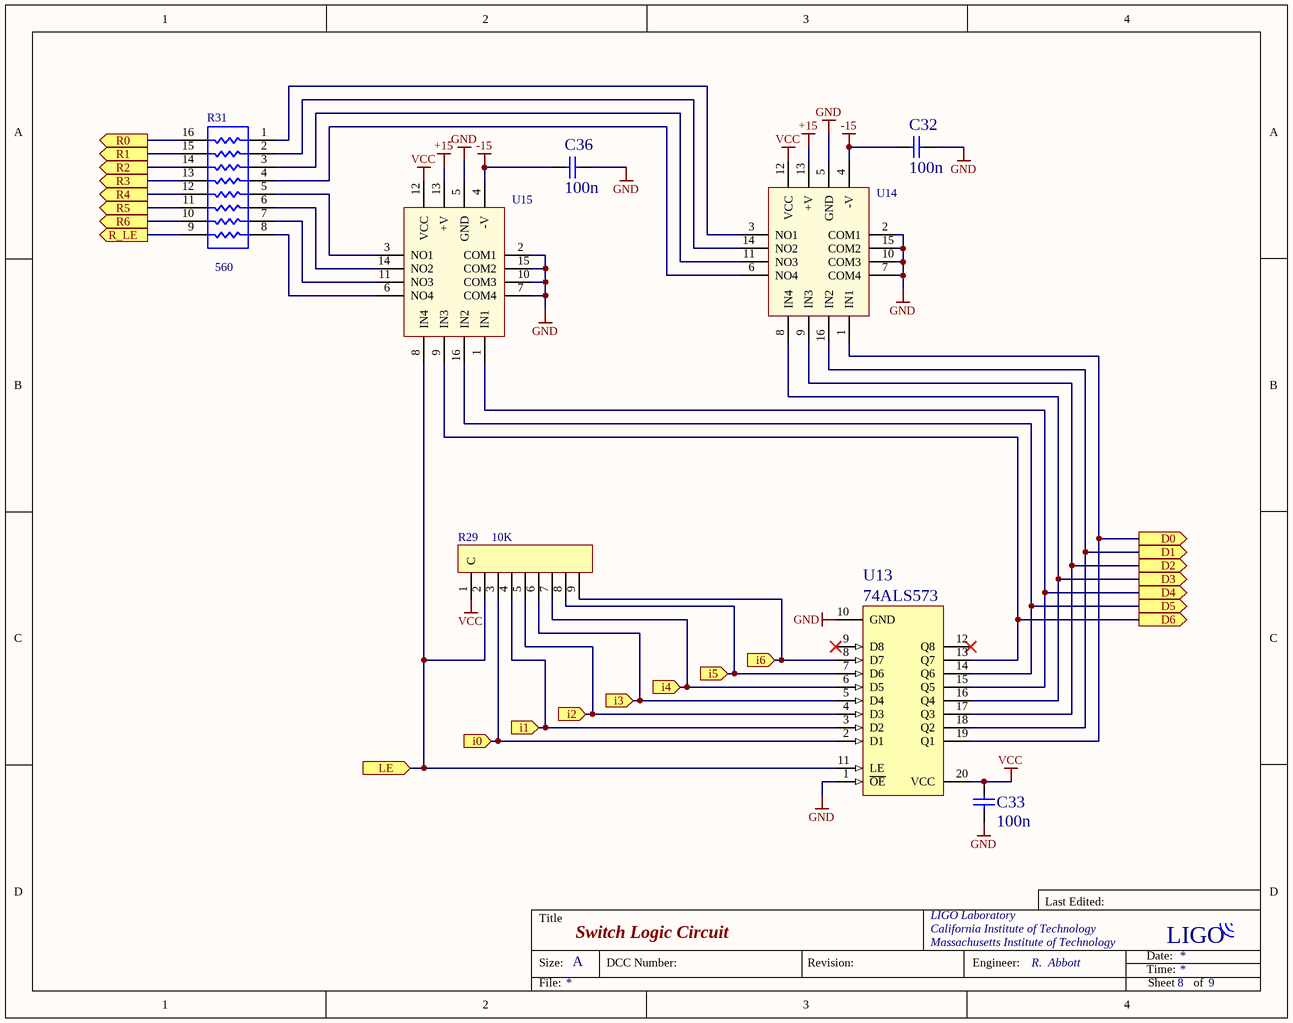
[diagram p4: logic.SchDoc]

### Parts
C32  100n  [3216[1206]]
C33  100n  [3216[1206]]
C36  100n  [3216[1206]]
R29  10K  [SRT9]
R31  560  [SOP127P760X300-16M]
U13  74ALS573  [DW020_M]
U14  DG412  [SOIC16]  (value not drawn)
U15  DG412  [SOIC16]  (value not drawn)

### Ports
D0 (out), D1 (out), D2 (out), D3 (out), D4 (out), D5 (out), D6 (out), i0 (in), i1 (in), i2 (in), i3 (in), i4 (in), i5 (in), i6 (in), LE (in), R0 (out), R1 (out), R2 (out), R3 (out), R4 (out), R5 (out), R6 (out), R_LE (out)

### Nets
+15: U14.13(+V) U15.13(+V)
-15: C32.2 C36.2 U14.4(-V) U15.4(-V)
GND: C32.1 C33.1 C36.1 U13.1(~{OE}) U13.10(GND) U14.2(COM1) U14.5(GND) U14.7(COM4) U14.10(COM3) U14.15(COM2) U15.2(COM1) U15.5(GND) U15.7(COM4) U15.10(COM3) U15.15(COM2)
VCC: C33.2 R29.1(C) U13.20(VCC) U14.12(VCC) U15.12(VCC)
D0: U13.19(Q1) U14.1(IN1) ; port D0
D1: U13.18(Q2) U14.16(IN2) ; port D1
D2: U13.17(Q3) U14.9(IN3) ; port D2
D3: U13.16(Q4) U14.8(IN4) ; port D3
D4: U13.15(Q5) U15.1(IN1) ; port D4
D5: U13.14(Q6) U15.16(IN2) ; port D5
D6: U13.13(Q7) U15.9(IN3) ; port D6
i0: R29.3 U13.2(D1) ; port i0
i1: R29.4 U13.3(D2) ; port i1
i2: R29.5 U13.4(D3) ; port i2
i3: R29.6 U13.5(D4) ; port i3
i4: R29.7 U13.6(D5) ; port i4
i5: R29.8 U13.7(D6) ; port i5
i6: R29.9 U13.8(D7) ; port i6
LE: R29.2 U13.11(LE) U15.8(IN4) ; port LE
R0: R31.16 ; port R0
R1: R31.15 ; port R1
R2: R31.14 ; port R2
R3: R31.13 ; port R3
R4: R31.12 ; port R4
R5: R31.11 ; port R5
R6: R31.10 ; port R6
R_LE: R31.9 ; port R_LE
NetR31_1: R31.1 U14.3(NO1)
NetR31_2: R31.2 U14.14(NO2)
NetR31_3: R31.3 U14.11(NO3)
NetR31_4: R31.4 U14.6(NO4)
NetR31_5: R31.5 U15.3(NO1)
NetR31_6: R31.6 U15.14(NO2)
NetR31_7: R31.7 U15.11(NO3)
NetR31_8: R31.8 U15.6(NO4)

Not connected (* = marked no-connect by the designer): U13 9(D8)* 12(Q8)*

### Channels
U_logic_A: designators end in _U_logic_A; ports D0=A1 D1=A2 D2=A3 D3=A4 D4=A5 D5=A6 D6=A7 i0=BI_0 i1=BI_1 i2=BI_2 i3=BI_3 i4=BI_4 i5=BI_5 i6=BI_6 LE=BI_7 R0=BO_0 R1=BO_1 R2=BO_2 R3=BO_3 R4=BO_4 R5=BO_5 R6=BO_6 R_LE=BO_7
U_logic_B: designators end in _U_logic_B; ports D0=B1 D1=B2 D2=B3 D3=B4 D4=B5 D5=B6 D6=B7 i0=BI_8 i1=BI_9 i2=BI_10 i3=BI_11 i4=BI_12 i5=BI_13 i6=BI_14 LE=BI_15 R0=BO_8 R1=BO_9 R2=BO_10 R3=BO_11 R4=BO_12 R5=BO_13 R6=BO_14 R_LE=BO_15
U_logic_C: designators end in _U_logic_C; ports D0=C1 D1=C2 D2=C3 D3=C4 D4=C5 D5=C6 D6=C7 i0=BI_16 i1=BI_17 i2=BI_18 i3=BI_19 i4=BI_20 i5=BI_21 i6=BI_22 LE=BI_23 R0=BO_16 R1=BO_17 R2=BO_18 R3=BO_19 R4=BO_20 R5=BO_21 R6=BO_22 R_LE=BO_23
U_logic_D: designators end in _U_logic_D; ports D0=D1 D1=D2 D2=D3 D3=D4 D4=D5 D5=D6 D6=D7 i0=BI_24 i1=BI_25 i2=BI_26 i3=BI_27 i4=BI_28 i5=BI_29 i6=BI_30 LE=BI_31 R0=BO_24 R1=BO_25 R2=BO_26 R3=BO_27 R4=BO_28 R5=BO_29 R6=BO_30 R_LE=BO_31

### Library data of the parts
C32 C33 C36 = Cap: Capacitor
R29 = RES_BUS_8: 8 Bus Resistor
R31 = Res Pack3: Isolated Resistor Network
U13 = SN74ALS573CDW: Octal D-Type Transparent Latches with 3-State Outputs
U14 U15 = DG412: Quad Analog SPST NO Switch

## Sheet filter2.SchDoc: Zero-pole Stage (Dewhitening)
size A; SchematicNumber: DYYYYYYY-VX; PcbNumber: DXXXXXXX-VX; LastEdit: 06 Oct 2010; Organization: LIGO Laboratory; Address1: California Institute of Technology; Address2: Massachusetts Institute of Technology; DocumentNumber: D2500133; Revision: 1; SheetNumber: 7; SheetTotal: 9; Engineer: R. Abbott/D. Sigg; PageSetup: Record=PageOptions¦CenterHorizontal=True¦CenterVertical=True¦PrintScale=1.40¦XCorrection=1.00¦YCorrection=1.00¦PrintKind=0¦BorderSize=5000000¦LeftOffset=0¦BottomOffset=0¦Orientation=2¦PaperLength=4318¦PaperWidth=2794¦Scale=100¦PaperSource=7¦PrintQuality=600¦MediaType=1¦DitherType=10¦PaperKind=11x17¦PrintScaleMode=1
Used 12 times, as channels PZ1_b, PZ2_b, PZ3_b, PZ1_a, PZ2_a, PZ3_a, PZ1_c, PZ2_c, PZ3_c, PZ1_d, PZ2_d, PZ3_d. Parts and nets are listed once, with the designators drawn on the sheet.
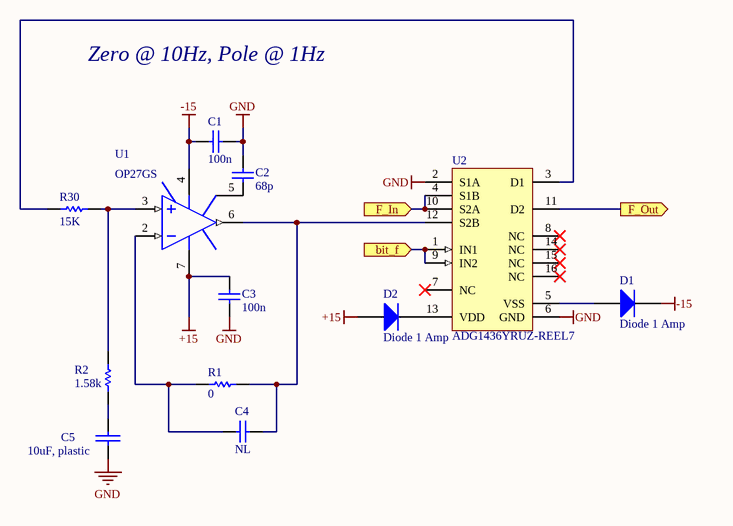
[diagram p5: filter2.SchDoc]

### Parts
C1  100n  [3216[1206]]
C2  68p  [3216[1206]]
C3  100n  [3216[1206]]
C4  NL  [3216[1206]]
C5  10uF, plastic  [ECQ-E1106KF_Side]
D1  value Diode 1 Amp  [sod123]  (hidden comment: 60V, 1A Schottky)
D2  value Diode 1 Amp  [sod123]  (hidden comment: 60V, 1A Schottky)
R1  0  [3216[1206]]
R2  1.58k  [3216[1206]]
R30  15K  [3216[1206]]
U1  OP27GS  [SOIC127P600-8N]
U2  ADG1436YRUZ-REEL7  [ADI-RU-16_L]

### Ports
bit_f (in), F_In (in), F_Out (out)

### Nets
+15: C3.2 D2.1(A) U1.7(V+)
-15: C1.2 D1.2(K) U1.4(V-)
GND: C1.1 C2.1 C3.1 C5.2 U2.2(S1A) U2.6(GND)
bit_f: U2.1(IN1) U2.9(IN2) ; port bit_f
F_In: U2.4(S1B) U2.10(S2A) ; port F_In
F_Out: U2.11(D2) ; port F_Out
NetC2_2: C2.2 U1.5(NUL)
NetC4_1: C4.1 R1.2 U1.2(IN-)
NetC4_2: C4.2 R1.1 U1.6(OUT) U2.12(S2B)
NetC5_1: C5.1 R2.1
NetD1_1: D1.1(A) U2.5(VSS)
NetD2_2: D2.2(K) U2.13(VDD)
NetR2_2: R2.2 R30.1 U1.3(IN+)
NetR30_2: R30.2 U2.3(D1)

Not connected (* = marked no-connect by the designer): U1 1(NUL) 8(NC); U2 7(NC)* 8(NC)* 14(NC)* 15(NC)* 16(NC)*

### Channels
PZ1_b: designators end in _PZ1_b; ports bit_f=B5 F_In=NetTP15_1 F_Out=NetU2_PZ1_b_11
PZ2_b: designators end in _PZ2_b; ports bit_f=B6 F_In=NetU2_PZ1_b_11 F_Out=NetU2_PZ2_b_11
PZ3_b: designators end in _PZ3_b; ports bit_f=B7 F_In=NetU2_PZ2_b_11 F_Out=NetTP16_1
PZ1_a: designators end in _PZ1_a; ports bit_f=A5 F_In=NetTP2_1 F_Out=NetU2_PZ1_a_11
PZ2_a: designators end in _PZ2_a; ports bit_f=A6 F_In=NetU2_PZ1_a_11 F_Out=NetU2_PZ2_a_11
PZ3_a: designators end in _PZ3_a; ports bit_f=A7 F_In=NetU2_PZ2_a_11 F_Out=NetTP13_1
PZ1_c: designators end in _PZ1_c; ports bit_f=C5 F_In=NetTP18_1 F_Out=NetU2_PZ1_c_11
PZ2_c: designators end in _PZ2_c; ports bit_f=C6 F_In=NetU2_PZ1_c_11 F_Out=NetU2_PZ2_c_11
PZ3_c: designators end in _PZ3_c; ports bit_f=C7 F_In=NetU2_PZ2_c_11 F_Out=NetTP19_1
PZ1_d: designators end in _PZ1_d; ports bit_f=D5 F_In=NetTP21_1 F_Out=NetU2_PZ1_d_11
PZ2_d: designators end in _PZ2_d; ports bit_f=D6 F_In=NetU2_PZ1_d_11 F_Out=NetU2_PZ2_d_11
PZ3_d: designators end in _PZ3_d; ports bit_f=D7 F_In=NetU2_PZ2_d_11 F_Out=NetTP22_1

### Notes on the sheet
- Zero @ 10Hz, Pole @ 1Hz

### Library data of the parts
C1-C4 = Cap: Capacitor
C5 = MYCAP: Capacitor
D1 D2 = Diode: Diode 1 Amp
R1 R2 R30 = Res1: Resistor
U1 = OP184ES: Video Operational Amplifier
U2 = CMP-0793-00126-1: as U8 on sheet VGA2

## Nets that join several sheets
+15: dewhite_top (25 pins), 24dB_a (C26_24dB_a.2 D7_24dB_a.1 U9_24dB_a.7), 12dB_a (C26_12dB_a.2 D7_12dB_a.1 U9_12dB_a.7), 6dB_a (C26_6dB_a.2 D7_6dB_a.1 U9_6dB_a.7), 3dB_a (C26_3dB_a.2 D7_3dB_a.1 U9_3dB_a.7), U_diff_in_A (C28_U_diff_in_A.1 U10_U_diff_in_A.4), U_diff_out_A (C30_U_diff_out_A.1 U11_U_diff_out_A.8), U_logic_A (U14_U_logic_A.13 U15_U_logic_A.13), U_diff_in_B (C28_U_diff_in_B.1 U10_U_diff_in_B.4), U_diff_out_B (C30_U_diff_out_B.1 U11_U_diff_out_B.8), U_logic_B (U14_U_logic_B.13 U15_U_logic_B.13), U_diff_in_C (C28_U_diff_in_C.1 U10_U_diff_in_C.4), U_diff_out_C (C30_U_diff_out_C.1 U11_U_diff_out_C.8), U_logic_C (U14_U_logic_C.13 U15_U_logic_C.13), U_diff_in_D (C28_U_diff_in_D.1 U10_U_diff_in_D.4), U_diff_out_D (C30_U_diff_out_D.1 U11_U_diff_out_D.8), U_logic_D (U14_U_logic_D.13 U15_U_logic_D.13), 24dB_b (C26_24dB_b.2 D7_24dB_b.1 U9_24dB_b.7), 12dB_b (C26_12dB_b.2 D7_12dB_b.1 U9_12dB_b.7), 12dB_c (C26_12dB_c.2 D7_12dB_c.1 U9_12dB_c.7), 12dB_d (C26_12dB_d.2 D7_12dB_d.1 U9_12dB_d.7), 24dB_c (C26_24dB_c.2 D7_24dB_c.1 U9_24dB_c.7), 24dB_d (C26_24dB_d.2 D7_24dB_d.1 U9_24dB_d.7), 6dB_b (C26_6dB_b.2 D7_6dB_b.1 U9_6dB_b.7), 6dB_c (C26_6dB_c.2 D7_6dB_c.1 U9_6dB_c.7), 6dB_d (C26_6dB_d.2 D7_6dB_d.1 U9_6dB_d.7), 3dB_b (C26_3dB_b.2 D7_3dB_b.1 U9_3dB_b.7), 3dB_c (C26_3dB_c.2 D7_3dB_c.1 U9_3dB_c.7), 3dB_d (C26_3dB_d.2 D7_3dB_d.1 U9_3dB_d.7), PZ1_b (C3_PZ1_b.2 D2_PZ1_b.1 U1_PZ1_b.7), PZ2_b (C3_PZ2_b.2 D2_PZ2_b.1 U1_PZ2_b.7), PZ3_b (C3_PZ3_b.2 D2_PZ3_b.1 U1_PZ3_b.7), PZ1_a (C3_PZ1_a.2 D2_PZ1_a.1 U1_PZ1_a.7), PZ2_a (C3_PZ2_a.2 D2_PZ2_a.1 U1_PZ2_a.7), PZ3_a (C3_PZ3_a.2 D2_PZ3_a.1 U1_PZ3_a.7), PZ1_c (C3_PZ1_c.2 D2_PZ1_c.1 U1_PZ1_c.7), PZ2_c (C3_PZ2_c.2 D2_PZ2_c.1 U1_PZ2_c.7), PZ3_c (C3_PZ3_c.2 D2_PZ3_c.1 U1_PZ3_c.7), PZ1_d (C3_PZ1_d.2 D2_PZ1_d.1 U1_PZ1_d.7), PZ2_d (C3_PZ2_d.2 D2_PZ2_d.1 U1_PZ2_d.7), PZ3_d (C3_PZ3_d.2 D2_PZ3_d.1 U1_PZ3_d.7)
-15: dewhite_top (16 pins), 24dB_a (C24_24dB_a.2 D6_24dB_a.2 U9_24dB_a.4), 12dB_a (C24_12dB_a.2 D6_12dB_a.2 U9_12dB_a.4), 6dB_a (C24_6dB_a.2 D6_6dB_a.2 U9_6dB_a.4), 3dB_a (C24_3dB_a.2 D6_3dB_a.2 U9_3dB_a.4), U_diff_in_A (C29_U_diff_in_A.1 U10_U_diff_in_A.13), U_diff_out_A (C31_U_diff_out_A.1 U11_U_diff_out_A.4), U_logic_A (C32_U_logic_A.2 C36_U_logic_A.2 U14_U_logic_A.4 U15_U_logic_A.4), U_diff_in_B (C29_U_diff_in_B.1 U10_U_diff_in_B.13), U_diff_out_B (C31_U_diff_out_B.1 U11_U_diff_out_B.4), U_logic_B (C32_U_logic_B.2 C36_U_logic_B.2 U14_U_logic_B.4 U15_U_logic_B.4), U_diff_in_C (C29_U_diff_in_C.1 U10_U_diff_in_C.13), U_diff_out_C (C31_U_diff_out_C.1 U11_U_diff_out_C.4), U_logic_C (C32_U_logic_C.2 C36_U_logic_C.2 U14_U_logic_C.4 U15_U_logic_C.4), U_diff_in_D (C29_U_diff_in_D.1 U10_U_diff_in_D.13), U_diff_out_D (C31_U_diff_out_D.1 U11_U_diff_out_D.4), U_logic_D (C32_U_logic_D.2 C36_U_logic_D.2 U14_U_logic_D.4 U15_U_logic_D.4), 24dB_b (C24_24dB_b.2 D6_24dB_b.2 U9_24dB_b.4), 12dB_b (C24_12dB_b.2 D6_12dB_b.2 U9_12dB_b.4), 12dB_c (C24_12dB_c.2 D6_12dB_c.2 U9_12dB_c.4), 12dB_d (C24_12dB_d.2 D6_12dB_d.2 U9_12dB_d.4), 24dB_c (C24_24dB_c.2 D6_24dB_c.2 U9_24dB_c.4), 24dB_d (C24_24dB_d.2 D6_24dB_d.2 U9_24dB_d.4), 6dB_b (C24_6dB_b.2 D6_6dB_b.2 U9_6dB_b.4), 6dB_c (C24_6dB_c.2 D6_6dB_c.2 U9_6dB_c.4), 6dB_d (C24_6dB_d.2 D6_6dB_d.2 U9_6dB_d.4), 3dB_b (C24_3dB_b.2 D6_3dB_b.2 U9_3dB_b.4), 3dB_c (C24_3dB_c.2 D6_3dB_c.2 U9_3dB_c.4), 3dB_d (C24_3dB_d.2 D6_3dB_d.2 U9_3dB_d.4), PZ1_b (C1_PZ1_b.2 D1_PZ1_b.2 U1_PZ1_b.4), PZ2_b (C1_PZ2_b.2 D1_PZ2_b.2 U1_PZ2_b.4), PZ3_b (C1_PZ3_b.2 D1_PZ3_b.2 U1_PZ3_b.4), PZ1_a (C1_PZ1_a.2 D1_PZ1_a.2 U1_PZ1_a.4), PZ2_a (C1_PZ2_a.2 D1_PZ2_a.2 U1_PZ2_a.4), PZ3_a (C1_PZ3_a.2 D1_PZ3_a.2 U1_PZ3_a.4), PZ1_c (C1_PZ1_c.2 D1_PZ1_c.2 U1_PZ1_c.4), PZ2_c (C1_PZ2_c.2 D1_PZ2_c.2 U1_PZ2_c.4), PZ3_c (C1_PZ3_c.2 D1_PZ3_c.2 U1_PZ3_c.4), PZ1_d (C1_PZ1_d.2 D1_PZ1_d.2 U1_PZ1_d.4), PZ2_d (C1_PZ2_d.2 D1_PZ2_d.2 U1_PZ2_d.4), PZ3_d (C1_PZ3_d.2 D1_PZ3_d.2 U1_PZ3_d.4)
GND: dewhite_top (38 pins), 24dB_a (6 pins), 12dB_a (6 pins), 6dB_a (6 pins), 3dB_a (6 pins), U_diff_in_A (7 pins), U_diff_out_A (C30_U_diff_out_A.2 C31_U_diff_out_A.2 U11_U_diff_out_A.5), U_logic_A (15 pins), U_diff_in_B (7 pins), U_diff_out_B (C30_U_diff_out_B.2 C31_U_diff_out_B.2 U11_U_diff_out_B.5), U_logic_B (15 pins), U_diff_in_C (7 pins), U_diff_out_C (C30_U_diff_out_C.2 C31_U_diff_out_C.2 U11_U_diff_out_C.5), U_logic_C (15 pins), U_diff_in_D (7 pins), U_diff_out_D (C30_U_diff_out_D.2 C31_U_diff_out_D.2 U11_U_diff_out_D.5), U_logic_D (15 pins), 24dB_b (6 pins), 12dB_b (6 pins), 12dB_c (6 pins), 12dB_d (6 pins), 24dB_c (6 pins), 24dB_d (6 pins), 6dB_b (6 pins), 6dB_c (6 pins), 6dB_d (6 pins), 3dB_b (6 pins), 3dB_c (6 pins), 3dB_d (6 pins), PZ1_b (6 pins), PZ2_b (6 pins), PZ3_b (6 pins), PZ1_a (6 pins), PZ2_a (6 pins), PZ3_a (6 pins), PZ1_c (6 pins), PZ2_c (6 pins), PZ3_c (6 pins), PZ1_d (6 pins), PZ2_d (6 pins), PZ3_d (6 pins)
VCC: dewhite_top (5 pins), U_logic_A (5 pins), U_logic_B (5 pins), U_logic_C (5 pins), U_logic_D (5 pins)
A1: 24dB_a (U8_24dB_a.1 U8_24dB_a.9), U_logic_A (U13_U_logic_A.19 U14_U_logic_A.1)
A2: 12dB_a (U8_12dB_a.1 U8_12dB_a.9), U_logic_A (U13_U_logic_A.18 U14_U_logic_A.16)
A3: 6dB_a (U8_6dB_a.1 U8_6dB_a.9), U_logic_A (U13_U_logic_A.17 U14_U_logic_A.9)
A4: 3dB_a (U8_3dB_a.1 U8_3dB_a.9), U_logic_A (U13_U_logic_A.16 U14_U_logic_A.8)
A5: U_logic_A (U13_U_logic_A.15 U15_U_logic_A.1), PZ1_a (U2_PZ1_a.1 U2_PZ1_a.9)
A6: U_logic_A (U13_U_logic_A.14 U15_U_logic_A.16), PZ2_a (U2_PZ2_a.1 U2_PZ2_a.9)
A7: U_logic_A (U13_U_logic_A.13 U15_U_logic_A.9), PZ3_a (U2_PZ3_a.1 U2_PZ3_a.9)
AN_1: dewhite_top (IN1.2 J5.9), U_diff_in_A (R22_U_diff_in_A.1 R33_U_diff_in_A.2)
AN_2: dewhite_top (IN2.2 J5.10), U_diff_in_B (R22_U_diff_in_B.1 R33_U_diff_in_B.2)
AN_3: dewhite_top (IN3.2 J5.11), U_diff_in_C (R22_U_diff_in_C.1 R33_U_diff_in_C.2)
AN_4: dewhite_top (IN4.2 J5.12), U_diff_in_D (R22_U_diff_in_D.1 R33_U_diff_in_D.2)
AP_1: dewhite_top (IN1.1 J5.1), U_diff_in_A (R14_U_diff_in_A.2 R32_U_diff_in_A.2)
AP_2: dewhite_top (IN2.1 J5.2), U_diff_in_B (R14_U_diff_in_B.2 R32_U_diff_in_B.2)
AP_3: dewhite_top (IN3.1 J5.3), U_diff_in_C (R14_U_diff_in_C.2 R32_U_diff_in_C.2)
AP_4: dewhite_top (IN4.1 J5.4), U_diff_in_D (R14_U_diff_in_D.2 R32_U_diff_in_D.2)
B1: U_logic_B (U13_U_logic_B.19 U14_U_logic_B.1), 24dB_b (U8_24dB_b.1 U8_24dB_b.9)
B2: U_logic_B (U13_U_logic_B.18 U14_U_logic_B.16), 12dB_b (U8_12dB_b.1 U8_12dB_b.9)
B3: U_logic_B (U13_U_logic_B.17 U14_U_logic_B.9), 6dB_b (U8_6dB_b.1 U8_6dB_b.9)
B4: U_logic_B (U13_U_logic_B.16 U14_U_logic_B.8), 3dB_b (U8_3dB_b.1 U8_3dB_b.9)
B5: U_logic_B (U13_U_logic_B.15 U15_U_logic_B.1), PZ1_b (U2_PZ1_b.1 U2_PZ1_b.9)
B6: U_logic_B (U13_U_logic_B.14 U15_U_logic_B.16), PZ2_b (U2_PZ2_b.1 U2_PZ2_b.9)
B7: U_logic_B (U13_U_logic_B.13 U15_U_logic_B.9), PZ3_b (U2_PZ3_b.1 U2_PZ3_b.9)
BI_0: dewhite_top (P1.2 P2.3), U_logic_A (R29_U_logic_A.3 U13_U_logic_A.2)
BI_1: dewhite_top (P1.3 P2.5), U_logic_A (R29_U_logic_A.4 U13_U_logic_A.3)
BI_2: dewhite_top (P1.4 P2.7), U_logic_A (R29_U_logic_A.5 U13_U_logic_A.4)
BI_3: dewhite_top (P1.5 P2.9), U_logic_A (R29_U_logic_A.6 U13_U_logic_A.5)
BI_4: dewhite_top (P1.6 P2.11), U_logic_A (R29_U_logic_A.7 U13_U_logic_A.6)
BI_5: dewhite_top (P1.7 P2.13), U_logic_A (R29_U_logic_A.8 U13_U_logic_A.7)
BI_6: dewhite_top (P1.8 P2.15), U_logic_A (R29_U_logic_A.9 U13_U_logic_A.8)
BI_7: dewhite_top (P1.9 P2.17), U_logic_A (R29_U_logic_A.2 U13_U_logic_A.11 U15_U_logic_A.8)
BI_8: dewhite_top (P1.10 P2.19), U_logic_B (R29_U_logic_B.3 U13_U_logic_B.2)
BI_9: dewhite_top (P1.11 P2.21), U_logic_B (R29_U_logic_B.4 U13_U_logic_B.3)
BI_10: dewhite_top (P1.12 P2.23), U_logic_B (R29_U_logic_B.5 U13_U_logic_B.4)
BI_11: dewhite_top (P1.13 P2.25), U_logic_B (R29_U_logic_B.6 U13_U_logic_B.5)
BI_12: dewhite_top (P1.14 P2.27), U_logic_B (R29_U_logic_B.7 U13_U_logic_B.6)
BI_13: dewhite_top (P1.15 P2.29), U_logic_B (R29_U_logic_B.8 U13_U_logic_B.7)
BI_14: dewhite_top (P1.16 P2.31), U_logic_B (R29_U_logic_B.9 U13_U_logic_B.8)
BI_15: dewhite_top (P1.17 P2.33), U_logic_B (R29_U_logic_B.2 U13_U_logic_B.11 U15_U_logic_B.8)
BI_16: dewhite_top (P1.21 P2.4), U_logic_C (R29_U_logic_C.3 U13_U_logic_C.2)
BI_17: dewhite_top (P1.22 P2.6), U_logic_C (R29_U_logic_C.4 U13_U_logic_C.3)
BI_18: dewhite_top (P1.23 P2.8), U_logic_C (R29_U_logic_C.5 U13_U_logic_C.4)
BI_19: dewhite_top (P1.24 P2.10), U_logic_C (R29_U_logic_C.6 U13_U_logic_C.5)
BI_20: dewhite_top (P1.25 P2.12), U_logic_C (R29_U_logic_C.7 U13_U_logic_C.6)
BI_21: dewhite_top (P1.26 P2.14), U_logic_C (R29_U_logic_C.8 U13_U_logic_C.7)
BI_22: dewhite_top (P1.27 P2.16), U_logic_C (R29_U_logic_C.9 U13_U_logic_C.8)
BI_23: dewhite_top (P1.28 P2.18), U_logic_C (R29_U_logic_C.2 U13_U_logic_C.11 U15_U_logic_C.8)
BI_24: dewhite_top (P1.29 P2.20), U_logic_D (R29_U_logic_D.3 U13_U_logic_D.2)
BI_25: dewhite_top (P1.30 P2.22), U_logic_D (R29_U_logic_D.4 U13_U_logic_D.3)
BI_26: dewhite_top (P1.31 P2.24), U_logic_D (R29_U_logic_D.5 U13_U_logic_D.4)
BI_27: dewhite_top (P1.32 P2.26), U_logic_D (R29_U_logic_D.6 U13_U_logic_D.5)
BI_28: dewhite_top (P1.33 P2.28), U_logic_D (R29_U_logic_D.7 U13_U_logic_D.6)
BI_29: dewhite_top (P1.34 P2.30), U_logic_D (R29_U_logic_D.8 U13_U_logic_D.7)
BI_30: dewhite_top (P1.35 P2.32), U_logic_D (R29_U_logic_D.9 U13_U_logic_D.8)
BI_31: dewhite_top (P1.36 P2.34), U_logic_D (R29_U_logic_D.2 U13_U_logic_D.11 U15_U_logic_D.8)
BO_0: dewhite_top (P3.2), U_logic_A (R31_U_logic_A.16)
BO_1: dewhite_top (P3.3), U_logic_A (R31_U_logic_A.15)
BO_2: dewhite_top (P3.4), U_logic_A (R31_U_logic_A.14)
BO_3: dewhite_top (P3.5), U_logic_A (R31_U_logic_A.13)
BO_4: dewhite_top (P3.6), U_logic_A (R31_U_logic_A.12)
BO_5: dewhite_top (P3.7), U_logic_A (R31_U_logic_A.11)
BO_6: dewhite_top (P3.8), U_logic_A (R31_U_logic_A.10)
BO_7: dewhite_top (P3.9), U_logic_A (R31_U_logic_A.9)
BO_8: dewhite_top (P3.10), U_logic_B (R31_U_logic_B.16)
BO_9: dewhite_top (P3.11), U_logic_B (R31_U_logic_B.15)
BO_10: dewhite_top (P3.12), U_logic_B (R31_U_logic_B.14)
BO_11: dewhite_top (P3.13), U_logic_B (R31_U_logic_B.13)
BO_12: dewhite_top (P3.14), U_logic_B (R31_U_logic_B.12)
BO_13: dewhite_top (P3.15), U_logic_B (R31_U_logic_B.11)
BO_14: dewhite_top (P3.16), U_logic_B (R31_U_logic_B.10)
BO_15: dewhite_top (P3.17), U_logic_B (R31_U_logic_B.9)
BO_16: dewhite_top (P3.21), U_logic_C (R31_U_logic_C.16)
BO_17: dewhite_top (P3.22), U_logic_C (R31_U_logic_C.15)
BO_18: dewhite_top (P3.23), U_logic_C (R31_U_logic_C.14)
BO_19: dewhite_top (P3.24), U_logic_C (R31_U_logic_C.13)
BO_20: dewhite_top (P3.25), U_logic_C (R31_U_logic_C.12)
BO_21: dewhite_top (P3.26), U_logic_C (R31_U_logic_C.11)
BO_22: dewhite_top (P3.27), U_logic_C (R31_U_logic_C.10)
BO_23: dewhite_top (P3.28), U_logic_C (R31_U_logic_C.9)
BO_24: dewhite_top (P3.29), U_logic_D (R31_U_logic_D.16)
BO_25: dewhite_top (P3.30), U_logic_D (R31_U_logic_D.15)
BO_26: dewhite_top (P3.31), U_logic_D (R31_U_logic_D.14)
BO_27: dewhite_top (P3.32), U_logic_D (R31_U_logic_D.13)
BO_28: dewhite_top (P3.33), U_logic_D (R31_U_logic_D.12)
BO_29: dewhite_top (P3.34), U_logic_D (R31_U_logic_D.11)
BO_30: dewhite_top (P3.35), U_logic_D (R31_U_logic_D.10)
BO_31: dewhite_top (P3.36), U_logic_D (R31_U_logic_D.9)
C1: U_logic_C (U13_U_logic_C.19 U14_U_logic_C.1), 24dB_c (U8_24dB_c.1 U8_24dB_c.9)
C2: U_logic_C (U13_U_logic_C.18 U14_U_logic_C.16), 12dB_c (U8_12dB_c.1 U8_12dB_c.9)
C3: U_logic_C (U13_U_logic_C.17 U14_U_logic_C.9), 6dB_c (U8_6dB_c.1 U8_6dB_c.9)
C4: U_logic_C (U13_U_logic_C.16 U14_U_logic_C.8), 3dB_c (U8_3dB_c.1 U8_3dB_c.9)
C5: U_logic_C (U13_U_logic_C.15 U15_U_logic_C.1), PZ1_c (U2_PZ1_c.1 U2_PZ1_c.9)
C6: U_logic_C (U13_U_logic_C.14 U15_U_logic_C.16), PZ2_c (U2_PZ2_c.1 U2_PZ2_c.9)
C7: U_logic_C (U13_U_logic_C.13 U15_U_logic_C.9), PZ3_c (U2_PZ3_c.1 U2_PZ3_c.9)
D1: U_logic_D (U13_U_logic_D.19 U14_U_logic_D.1), 24dB_d (U8_24dB_d.1 U8_24dB_d.9)
D2: U_logic_D (U13_U_logic_D.18 U14_U_logic_D.16), 12dB_d (U8_12dB_d.1 U8_12dB_d.9)
D3: U_logic_D (U13_U_logic_D.17 U14_U_logic_D.9), 6dB_d (U8_6dB_d.1 U8_6dB_d.9)
D4: U_logic_D (U13_U_logic_D.16 U14_U_logic_D.8), 3dB_d (U8_3dB_d.1 U8_3dB_d.9)
D5: U_logic_D (U13_U_logic_D.15 U15_U_logic_D.1), PZ1_d (U2_PZ1_d.1 U2_PZ1_d.9)
D6: U_logic_D (U13_U_logic_D.14 U15_U_logic_D.16), PZ2_d (U2_PZ2_d.1 U2_PZ2_d.9)
D7: U_logic_D (U13_U_logic_D.13 U15_U_logic_D.9), PZ3_d (U2_PZ3_d.1 U2_PZ3_d.9)
NetC39_U_diff_in_A_2: dewhite_top (TP1.1), 24dB_a (U8_24dB_a.4 U8_24dB_a.10), U_diff_in_A (C39_U_diff_in_A.2 R20_U_diff_in_A.1 U10_U_diff_in_A.10)
NetC39_U_diff_in_B_2: dewhite_top (TP14.1), U_diff_in_B (C39_U_diff_in_B.2 R20_U_diff_in_B.1 U10_U_diff_in_B.10), 24dB_b (U8_24dB_b.4 U8_24dB_b.10)
NetC39_U_diff_in_C_2: dewhite_top (TP17.1), U_diff_in_C (C39_U_diff_in_C.2 R20_U_diff_in_C.1 U10_U_diff_in_C.10), 24dB_c (U8_24dB_c.4 U8_24dB_c.10)
NetC39_U_diff_in_D_2: dewhite_top (TP20.1), U_diff_in_D (C39_U_diff_in_D.2 R20_U_diff_in_D.1 U10_U_diff_in_D.10), 24dB_d (U8_24dB_d.4 U8_24dB_d.10)
NetR3_2: dewhite_top (R3.2 U3.6), U_diff_out_A (R24_U_diff_out_A.1 R27_U_diff_out_A.1 TP8_U_diff_out_A.1 U11_U_diff_out_A.3)
NetR4_2: dewhite_top (R4.2 U4.6), U_diff_out_B (R24_U_diff_out_B.1 R27_U_diff_out_B.1 TP8_U_diff_out_B.1 U11_U_diff_out_B.3)
NetR5_2: dewhite_top (R5.2 U5.6), U_diff_out_C (R24_U_diff_out_C.1 R27_U_diff_out_C.1 TP8_U_diff_out_C.1 U11_U_diff_out_C.3)
NetR6_2: dewhite_top (R6.2 U6.6), U_diff_out_D (R24_U_diff_out_D.1 R27_U_diff_out_D.1 TP8_U_diff_out_D.1 U11_U_diff_out_D.3)
NetTP2_1: dewhite_top (TP2.1), 3dB_a (U8_3dB_a.11), PZ1_a (U2_PZ1_a.4 U2_PZ1_a.10)
NetTP13_1: dewhite_top (TP13.1 U3.3), PZ3_a (U2_PZ3_a.11)
NetTP15_1: dewhite_top (TP15.1), 3dB_b (U8_3dB_b.11), PZ1_b (U2_PZ1_b.4 U2_PZ1_b.10)
NetTP16_1: dewhite_top (TP16.1 U4.3), PZ3_b (U2_PZ3_b.11)
NetTP18_1: dewhite_top (TP18.1), 3dB_c (U8_3dB_c.11), PZ1_c (U2_PZ1_c.4 U2_PZ1_c.10)
NetTP19_1: dewhite_top (TP19.1 U5.3), PZ3_c (U2_PZ3_c.11)
NetTP21_1: dewhite_top (TP21.1), 3dB_d (U8_3dB_d.11), PZ1_d (U2_PZ1_d.4 U2_PZ1_d.10)
NetTP22_1: dewhite_top (TP22.1 U6.3), PZ3_d (U2_PZ3_d.11)
NetU2_PZ1_a_11: PZ1_a (U2_PZ1_a.11), PZ2_a (U2_PZ2_a.4 U2_PZ2_a.10)
NetU2_PZ1_b_11: PZ1_b (U2_PZ1_b.11), PZ2_b (U2_PZ2_b.4 U2_PZ2_b.10)
NetU2_PZ1_c_11: PZ1_c (U2_PZ1_c.11), PZ2_c (U2_PZ2_c.4 U2_PZ2_c.10)
NetU2_PZ1_d_11: PZ1_d (U2_PZ1_d.11), PZ2_d (U2_PZ2_d.4 U2_PZ2_d.10)
NetU2_PZ2_a_11: PZ2_a (U2_PZ2_a.11), PZ3_a (U2_PZ3_a.4 U2_PZ3_a.10)
NetU2_PZ2_b_11: PZ2_b (U2_PZ2_b.11), PZ3_b (U2_PZ3_b.4 U2_PZ3_b.10)
NetU2_PZ2_c_11: PZ2_c (U2_PZ2_c.11), PZ3_c (U2_PZ3_c.4 U2_PZ3_c.10)
NetU2_PZ2_d_11: PZ2_d (U2_PZ2_d.11), PZ3_d (U2_PZ3_d.4 U2_PZ3_d.10)
NetU8_3dB_a_4: 6dB_a (U8_6dB_a.11), 3dB_a (U8_3dB_a.4 U8_3dB_a.10)
NetU8_3dB_b_4: 6dB_b (U8_6dB_b.11), 3dB_b (U8_3dB_b.4 U8_3dB_b.10)
NetU8_3dB_c_4: 6dB_c (U8_6dB_c.11), 3dB_c (U8_3dB_c.4 U8_3dB_c.10)
NetU8_3dB_d_4: 6dB_d (U8_6dB_d.11), 3dB_d (U8_3dB_d.4 U8_3dB_d.10)
NetU8_6dB_a_4: 12dB_a (U8_12dB_a.11), 6dB_a (U8_6dB_a.4 U8_6dB_a.10)
NetU8_6dB_b_4: 12dB_b (U8_12dB_b.11), 6dB_b (U8_6dB_b.4 U8_6dB_b.10)
NetU8_6dB_c_4: 12dB_c (U8_12dB_c.11), 6dB_c (U8_6dB_c.4 U8_6dB_c.10)
NetU8_6dB_d_4: 12dB_d (U8_12dB_d.11), 6dB_d (U8_6dB_d.4 U8_6dB_d.10)
NetU8_12dB_a_4: 24dB_a (U8_24dB_a.11), 12dB_a (U8_12dB_a.4 U8_12dB_a.10)
NetU8_12dB_b_4: 24dB_b (U8_24dB_b.11), 12dB_b (U8_12dB_b.4 U8_12dB_b.10)
NetU8_12dB_c_4: 12dB_c (U8_12dB_c.4 U8_12dB_c.10), 24dB_c (U8_24dB_c.11)
NetU8_12dB_d_4: 12dB_d (U8_12dB_d.4 U8_12dB_d.10), 24dB_d (U8_24dB_d.11)
WN1: dewhite_top (J6.6 OUT1.2), U_diff_out_A (R26_U_diff_out_A.2)
WN2: dewhite_top (J6.7 OUT2.2), U_diff_out_B (R26_U_diff_out_B.2)
WN3: dewhite_top (J6.8 OUT3.2), U_diff_out_C (R26_U_diff_out_C.2)
WN4: dewhite_top (J6.9 OUT4.2), U_diff_out_D (R26_U_diff_out_D.2)
WP1: dewhite_top (J6.1 OUT1.1), U_diff_out_A (R23_U_diff_out_A.2)
WP2: dewhite_top (J6.2 OUT2.1), U_diff_out_B (R23_U_diff_out_B.2)
WP3: dewhite_top (J6.3 OUT3.1), U_diff_out_C (R23_U_diff_out_C.2)
WP4: dewhite_top (J6.4 OUT4.1), U_diff_out_D (R23_U_diff_out_D.2)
